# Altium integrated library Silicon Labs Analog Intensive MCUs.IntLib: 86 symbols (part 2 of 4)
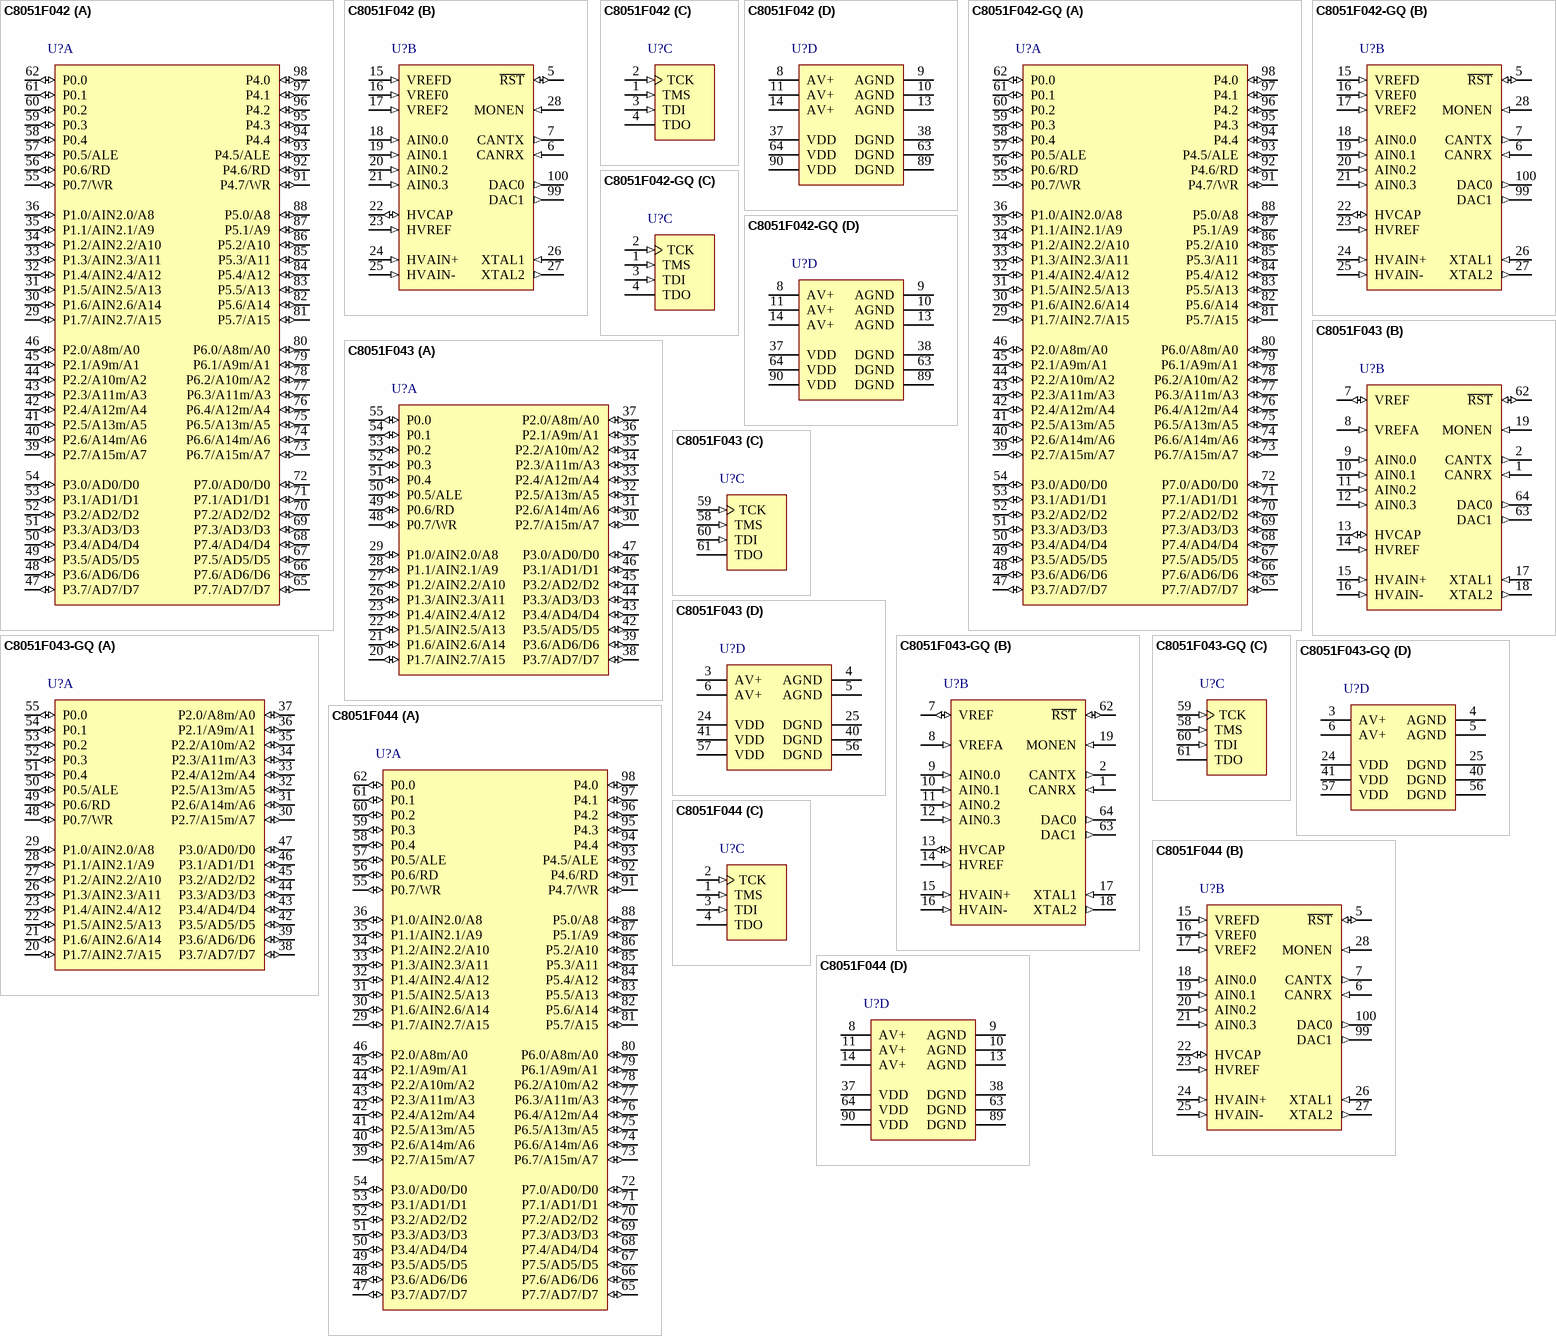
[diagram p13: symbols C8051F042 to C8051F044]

## C8051F042-GQ
designator U?
Mixed Signal 64KB ISP Flash MCU, 25 MIPS, 4352B RAM, 64 I/Os, 10-Bit & 8-Bit ADC, 12-Bit DAC, 100-Pin TQFP, Pb-Free; Manufacturer: Silicon Labs; PartNumber: C8051F042-GQ
footprint TQFP-100_N (Thin QFP, 100-Leads, Body 14x14mm, Pitch 0.5mm, IPC Medium Density)
footprint TQFP-100_L (Thin QFP, 100-Leads, Body 14x14mm, Pitch 0.5mm, IPC High Density)
footprint TQFP-100_M (Thin QFP, 100-Leads, Body 14x14mm, Pitch 0.5mm, IPC Low Density)
part A pins: 29 P1.7/AIN2.7/A15 (io), 30 P1.6/AIN2.6/A14 (io), 31 P1.5/AIN2.5/A13 (io), 32 P1.4/AIN2.4/A12 (io), 33 P1.3/AIN2.3/A11 (io), 34 P1.2/AIN2.2/A10 (io), 35 P1.1/AIN2.1/A9 (io), 36 P1.0/AIN2.0/A8 (io), 39 P2.7/A15m/A7 (io), 40 P2.6/A14m/A6 (io), 41 P2.5/A13m/A5 (io), 42 P2.4/A12m/A4 (io), 43 P2.3/A11m/A3 (io), 44 P2.2/A10m/A2 (io), 45 P2.1/A9m/A1 (io), 46 P2.0/A8m/A0 (io), 47 P3.7/AD7/D7 (io), 48 P3.6/AD6/D6 (io), 49 P3.5/AD5/D5 (io), 50 P3.4/AD4/D4 (io), 51 P3.3/AD3/D3 (io), 52 P3.2/AD2/D2 (io), 53 P3.1/AD1/D1 (io), 54 P3.0/AD0/D0 (io), 55 P0.7/WR (io), 56 P0.6/RD (io), 57 P0.5/ALE (io), 58 P0.4 (io), 59 P0.3 (io), 60 P0.2 (io), 61 P0.1 (io), 62 P0.0 (io), 65 P7.7/AD7/D7 (io), 66 P7.6/AD6/D6 (io), 67 P7.5/AD5/D5 (io), 68 P7.4/AD4/D4 (io), 69 P7.3/AD3/D3 (io), 70 P7.2/AD2/D2 (io), 71 P7.1/AD1/D1 (io), 72 P7.0/AD0/D0 (io), 73 P6.7/A15m/A7 (io), 74 P6.6/A14m/A6 (io), 75 P6.5/A13m/A5 (io), 76 P6.4/A12m/A4 (io), 77 P6.3/A11m/A3 (io), 78 P6.2/A10m/A2 (io), 79 P6.1/A9m/A1 (io), 80 P6.0/A8m/A0 (io), 81 P5.7/A15 (io), 82 P5.6/A14 (io), 83 P5.5/A13 (io), 84 P5.4/A12 (io), 85 P5.3/A11 (io), 86 P5.2/A10 (io), 87 P5.1/A9 (io), 88 P5.0/A8 (io), 91 P4.7/WR (io), 92 P4.6/RD (io), 93 P4.5/ALE (io), 94 P4.4 (io), 95 P4.3 (io), 96 P4.2 (io), 97 P4.1 (io), 98 P4.0 (io)
part B pins: 5 ~{RST} (io), 6 CANRX (in), 7 CANTX (out), 15 VREFD (in), 16 VREF0 (in), 17 VREF2 (in), 18 AIN0.0 (in), 19 AIN0.1 (in), 20 AIN0.2 (in), 21 AIN0.3 (in), 22 HVCAP (io), 23 HVREF (in), 24 HVAIN+ (in), 25 HVAIN- (in), 26 XTAL1 (in), 27 XTAL2 (out), 28 MONEN (in), 99 DAC1 (out), 100 DAC0 (out)
part C pins: 1 TMS (in), 2 TCK (in), 3 TDI (in), 4 TDO (hiz)
part D pins: 8 AV+ (power), 9 AGND (power), 10 AGND (power), 11 AV+ (power), 13 AGND (power), 14 AV+ (power), 37 VDD (power), 38 DGND (power), 63 DGND (power), 64 VDD (power), 89 DGND (power), 90 VDD (power)

## C8051F043
designator U?
Mixed Signal 64KB ISP Flash MCU, 25 MIPS, 4352B RAM, 32 I/Os, 10-Bit & 8-Bit ADC, 12-Bit DAC, 64-Pin TQFP; Manufacturer: Silicon Labs; PartNumber: C8051F043
footprint TQFP-64_N (Thin QFP, 64-Leads, Body 10x10mm, Pitch 0.5mm, IPC Medium Density)
footprint TQFP-64_L (Thin QFP, 64-Leads, Body 10x10mm, Pitch 0.5mm, IPC High Density)
footprint TQFP-64_M (Thin QFP, 64-Leads, Body 10x10mm, Pitch 0.5mm, IPC Low Density)
part A pins: 20 P1.7/AIN2.7/A15 (io), 21 P1.6/AIN2.6/A14 (io), 22 P1.5/AIN2.5/A13 (io), 23 P1.4/AIN2.4/A12 (io), 26 P1.3/AIN2.3/A11 (io), 27 P1.2/AIN2.2/A10 (io), 28 P1.1/AIN2.1/A9 (io), 29 P1.0/AIN2.0/A8 (io), 30 P2.7/A15m/A7 (io), 31 P2.6/A14m/A6 (io), 32 P2.5/A13m/A5 (io), 33 P2.4/A12m/A4 (io), 34 P2.3/A11m/A3 (io), 35 P2.2/A10m/A2 (io), 36 P2.1/A9m/A1 (io), 37 P2.0/A8m/A0 (io), 38 P3.7/AD7/D7 (io), 39 P3.6/AD6/D6 (io), 42 P3.5/AD5/D5 (io), 43 P3.4/AD4/D4 (io), 44 P3.3/AD3/D3 (io), 45 P3.2/AD2/D2 (io), 46 P3.1/AD1/D1 (io), 47 P3.0/AD0/D0 (io), 48 P0.7/WR (io), 49 P0.6/RD (io), 50 P0.5/ALE (io), 51 P0.4 (io), 52 P0.3 (io), 53 P0.2 (io), 54 P0.1 (io), 55 P0.0 (io)
part B pins: 1 CANRX (in), 2 CANTX (out), 7 VREF (io), 8 VREFA (in), 9 AIN0.0 (in), 10 AIN0.1 (in), 11 AIN0.2 (in), 12 AIN0.3 (in), 13 HVCAP (io), 14 HVREF (in), 15 HVAIN+ (in), 16 HVAIN- (in), 17 XTAL1 (in), 18 XTAL2 (out), 19 MONEN (in), 62 ~{RST} (io), 63 DAC1 (out), 64 DAC0 (out)
part C pins: 58 TMS (in), 59 TCK (in), 60 TDI (in), 61 TDO (hiz)
part D pins: 3 AV+ (power), 4 AGND (power), 5 AGND (power), 6 AV+ (power), 24 VDD (power), 25 DGND (power), 40 DGND (power), 41 VDD (power), 56 DGND (power), 57 VDD (power)

## C8051F043-GQ
designator U?
Mixed Signal 64KB ISP Flash MCU, 25 MIPS, 4352B RAM, 32 I/Os, 10-Bit & 8-Bit ADC, 12-Bit DAC, 64-Pin TQFP, Pb-Free; Manufacturer: Silicon Labs; PartNumber: C8051F043-GQ
footprint TQFP-64_N (Thin QFP, 64-Leads, Body 10x10mm, Pitch 0.5mm, IPC Medium Density)
footprint TQFP-64_L (Thin QFP, 64-Leads, Body 10x10mm, Pitch 0.5mm, IPC High Density)
footprint TQFP-64_M (Thin QFP, 64-Leads, Body 10x10mm, Pitch 0.5mm, IPC Low Density)
part A pins: 20 P1.7/AIN2.7/A15 (io), 21 P1.6/AIN2.6/A14 (io), 22 P1.5/AIN2.5/A13 (io), 23 P1.4/AIN2.4/A12 (io), 26 P1.3/AIN2.3/A11 (io), 27 P1.2/AIN2.2/A10 (io), 28 P1.1/AIN2.1/A9 (io), 29 P1.0/AIN2.0/A8 (io), 30 P2.7/A15m/A7 (io), 31 P2.6/A14m/A6 (io), 32 P2.5/A13m/A5 (io), 33 P2.4/A12m/A4 (io), 34 P2.3/A11m/A3 (io), 35 P2.2/A10m/A2 (io), 36 P2.1/A9m/A1 (io), 37 P2.0/A8m/A0 (io), 38 P3.7/AD7/D7 (io), 39 P3.6/AD6/D6 (io), 42 P3.5/AD5/D5 (io), 43 P3.4/AD4/D4 (io), 44 P3.3/AD3/D3 (io), 45 P3.2/AD2/D2 (io), 46 P3.1/AD1/D1 (io), 47 P3.0/AD0/D0 (io), 48 P0.7/WR (io), 49 P0.6/RD (io), 50 P0.5/ALE (io), 51 P0.4 (io), 52 P0.3 (io), 53 P0.2 (io), 54 P0.1 (io), 55 P0.0 (io)
part B pins: 1 CANRX (in), 2 CANTX (out), 7 VREF (io), 8 VREFA (in), 9 AIN0.0 (in), 10 AIN0.1 (in), 11 AIN0.2 (in), 12 AIN0.3 (in), 13 HVCAP (io), 14 HVREF (in), 15 HVAIN+ (in), 16 HVAIN- (in), 17 XTAL1 (in), 18 XTAL2 (out), 19 MONEN (in), 62 ~{RST} (io), 63 DAC1 (out), 64 DAC0 (out)
part C pins: 58 TMS (in), 59 TCK (in), 60 TDI (in), 61 TDO (hiz)
part D pins: 3 AV+ (power), 4 AGND (power), 5 AGND (power), 6 AV+ (power), 24 VDD (power), 25 DGND (power), 40 DGND (power), 41 VDD (power), 56 DGND (power), 57 VDD (power)

## C8051F044
designator U?
Mixed Signal 64KB ISP Flash MCU, 25 MIPS, 4352B RAM, 64 I/Os, 10-Bit ADC, 100-Pin TQFP; Manufacturer: Silicon Labs; PartNumber: C8051F044
footprint TQFP-100_N (Thin QFP, 100-Leads, Body 14x14mm, Pitch 0.5mm, IPC Medium Density)
footprint TQFP-100_L (Thin QFP, 100-Leads, Body 14x14mm, Pitch 0.5mm, IPC High Density)
footprint TQFP-100_M (Thin QFP, 100-Leads, Body 14x14mm, Pitch 0.5mm, IPC Low Density)
part A pins: 29 P1.7/AIN2.7/A15 (io), 30 P1.6/AIN2.6/A14 (io), 31 P1.5/AIN2.5/A13 (io), 32 P1.4/AIN2.4/A12 (io), 33 P1.3/AIN2.3/A11 (io), 34 P1.2/AIN2.2/A10 (io), 35 P1.1/AIN2.1/A9 (io), 36 P1.0/AIN2.0/A8 (io), 39 P2.7/A15m/A7 (io), 40 P2.6/A14m/A6 (io), 41 P2.5/A13m/A5 (io), 42 P2.4/A12m/A4 (io), 43 P2.3/A11m/A3 (io), 44 P2.2/A10m/A2 (io), 45 P2.1/A9m/A1 (io), 46 P2.0/A8m/A0 (io), 47 P3.7/AD7/D7 (io), 48 P3.6/AD6/D6 (io), 49 P3.5/AD5/D5 (io), 50 P3.4/AD4/D4 (io), 51 P3.3/AD3/D3 (io), 52 P3.2/AD2/D2 (io), 53 P3.1/AD1/D1 (io), 54 P3.0/AD0/D0 (io), 55 P0.7/WR (io), 56 P0.6/RD (io), 57 P0.5/ALE (io), 58 P0.4 (io), 59 P0.3 (io), 60 P0.2 (io), 61 P0.1 (io), 62 P0.0 (io), 65 P7.7/AD7/D7 (io), 66 P7.6/AD6/D6 (io), 67 P7.5/AD5/D5 (io), 68 P7.4/AD4/D4 (io), 69 P7.3/AD3/D3 (io), 70 P7.2/AD2/D2 (io), 71 P7.1/AD1/D1 (io), 72 P7.0/AD0/D0 (io), 73 P6.7/A15m/A7 (io), 74 P6.6/A14m/A6 (io), 75 P6.5/A13m/A5 (io), 76 P6.4/A12m/A4 (io), 77 P6.3/A11m/A3 (io), 78 P6.2/A10m/A2 (io), 79 P6.1/A9m/A1 (io), 80 P6.0/A8m/A0 (io), 81 P5.7/A15 (io), 82 P5.6/A14 (io), 83 P5.5/A13 (io), 84 P5.4/A12 (io), 85 P5.3/A11 (io), 86 P5.2/A10 (io), 87 P5.1/A9 (io), 88 P5.0/A8 (io), 91 P4.7/WR (io), 92 P4.6/RD (io), 93 P4.5/ALE (io), 94 P4.4 (io), 95 P4.3 (io), 96 P4.2 (io), 97 P4.1 (io), 98 P4.0 (io)
part B pins: 5 ~{RST} (io), 6 CANRX (in), 7 CANTX (out), 15 VREFD (in), 16 VREF0 (in), 17 VREF2 (in), 18 AIN0.0 (in), 19 AIN0.1 (in), 20 AIN0.2 (in), 21 AIN0.3 (in), 22 HVCAP (io), 23 HVREF (in), 24 HVAIN+ (in), 25 HVAIN- (in), 26 XTAL1 (in), 27 XTAL2 (out), 28 MONEN (in), 99 DAC1 (out), 100 DAC0 (out)
part C pins: 1 TMS (in), 2 TCK (in), 3 TDI (in), 4 TDO (hiz)
part D pins: 8 AV+ (power), 9 AGND (power), 10 AGND (power), 11 AV+ (power), 13 AGND (power), 14 AV+ (power), 37 VDD (power), 38 DGND (power), 63 DGND (power), 64 VDD (power), 89 DGND (power), 90 VDD (power)

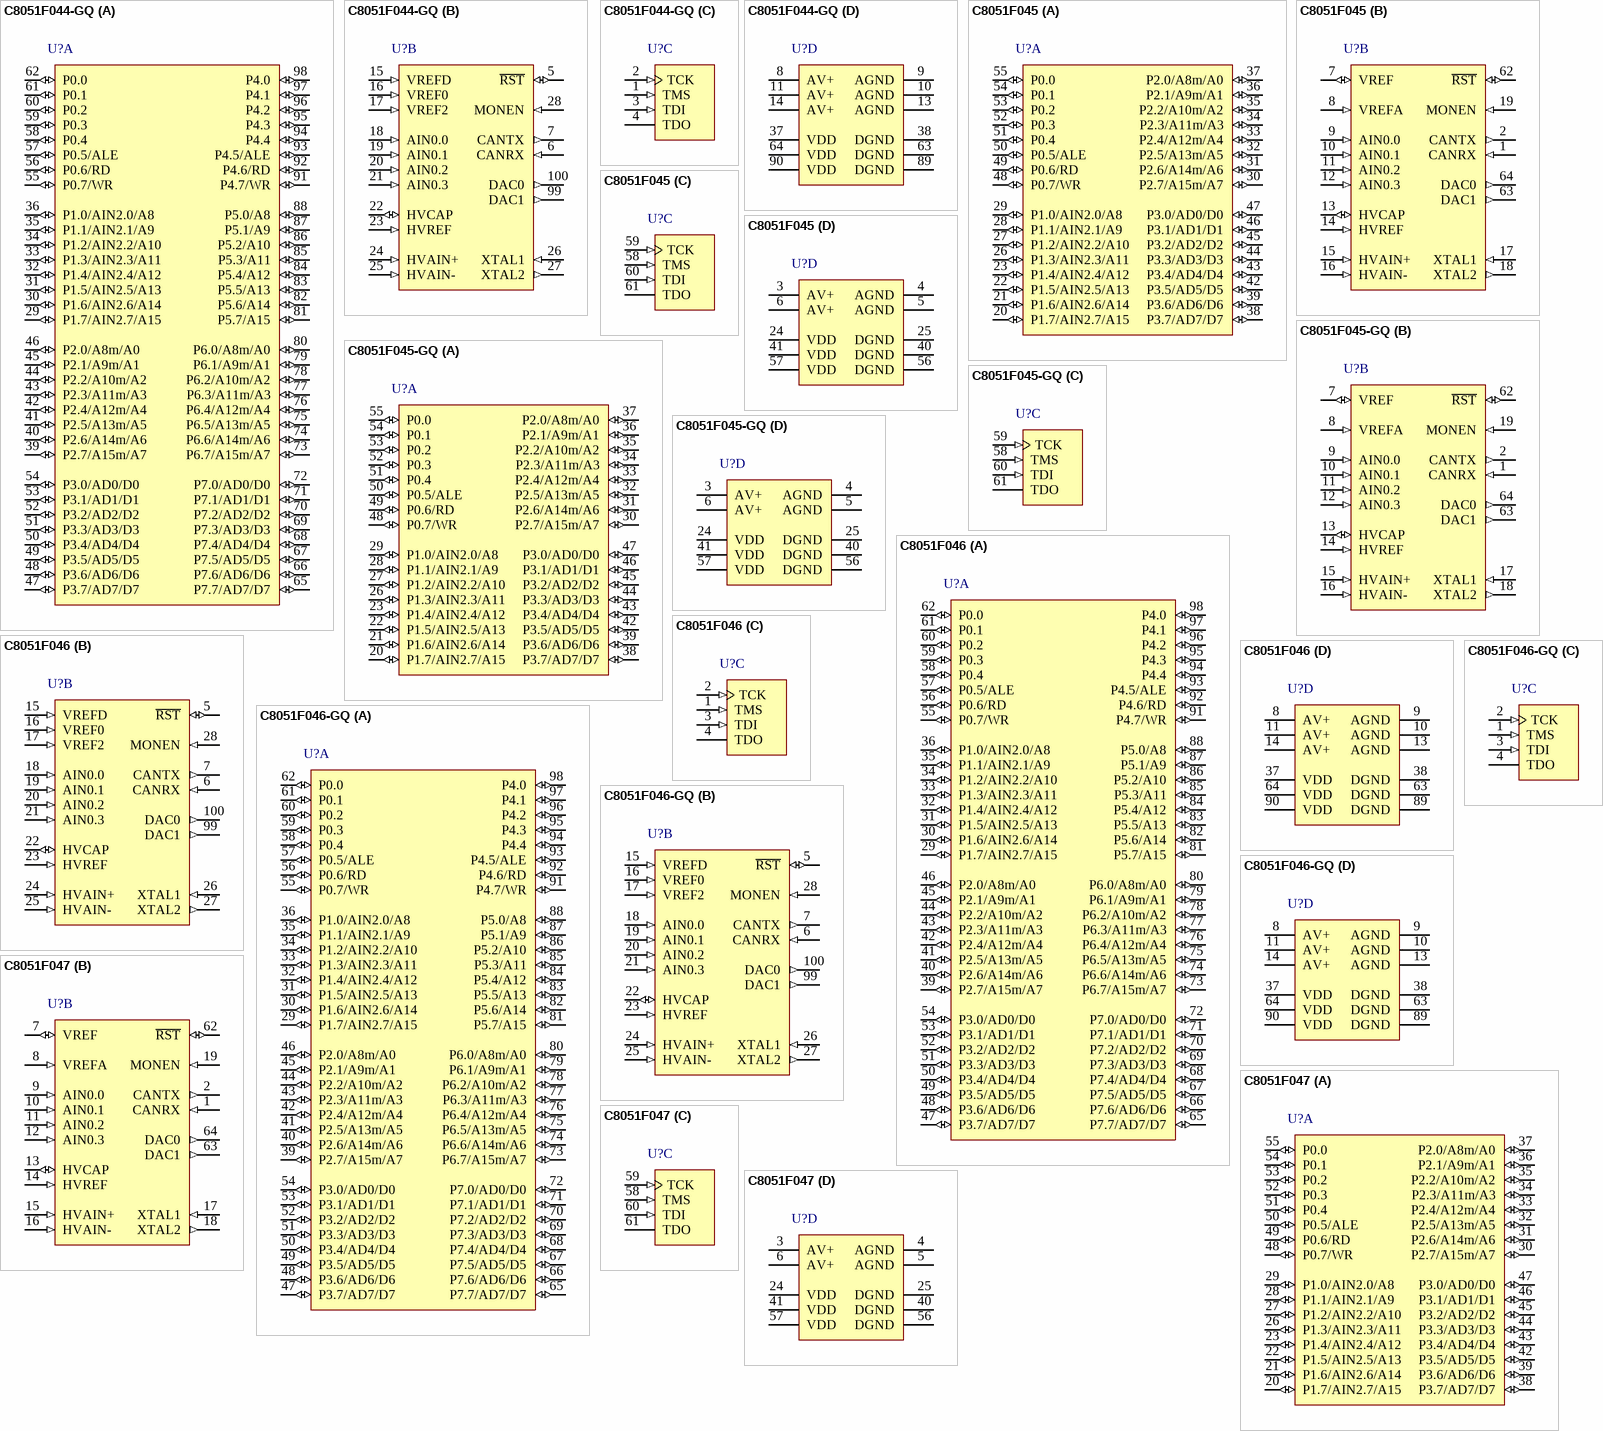
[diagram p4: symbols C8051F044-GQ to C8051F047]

## C8051F044-GQ
designator U?
Mixed Signal 64KB ISP Flash MCU, 25 MIPS, 4352B RAM, 64 I/Os, 10-Bit ADC, 100-Pin TQFP, Pb-Free; Manufacturer: Silicon Labs; PartNumber: C8051F044-GQ
footprint TQFP-100_N (Thin QFP, 100-Leads, Body 14x14mm, Pitch 0.5mm, IPC Medium Density)
footprint TQFP-100_L (Thin QFP, 100-Leads, Body 14x14mm, Pitch 0.5mm, IPC High Density)
footprint TQFP-100_M (Thin QFP, 100-Leads, Body 14x14mm, Pitch 0.5mm, IPC Low Density)
part A pins: 29 P1.7/AIN2.7/A15 (io), 30 P1.6/AIN2.6/A14 (io), 31 P1.5/AIN2.5/A13 (io), 32 P1.4/AIN2.4/A12 (io), 33 P1.3/AIN2.3/A11 (io), 34 P1.2/AIN2.2/A10 (io), 35 P1.1/AIN2.1/A9 (io), 36 P1.0/AIN2.0/A8 (io), 39 P2.7/A15m/A7 (io), 40 P2.6/A14m/A6 (io), 41 P2.5/A13m/A5 (io), 42 P2.4/A12m/A4 (io), 43 P2.3/A11m/A3 (io), 44 P2.2/A10m/A2 (io), 45 P2.1/A9m/A1 (io), 46 P2.0/A8m/A0 (io), 47 P3.7/AD7/D7 (io), 48 P3.6/AD6/D6 (io), 49 P3.5/AD5/D5 (io), 50 P3.4/AD4/D4 (io), 51 P3.3/AD3/D3 (io), 52 P3.2/AD2/D2 (io), 53 P3.1/AD1/D1 (io), 54 P3.0/AD0/D0 (io), 55 P0.7/WR (io), 56 P0.6/RD (io), 57 P0.5/ALE (io), 58 P0.4 (io), 59 P0.3 (io), 60 P0.2 (io), 61 P0.1 (io), 62 P0.0 (io), 65 P7.7/AD7/D7 (io), 66 P7.6/AD6/D6 (io), 67 P7.5/AD5/D5 (io), 68 P7.4/AD4/D4 (io), 69 P7.3/AD3/D3 (io), 70 P7.2/AD2/D2 (io), 71 P7.1/AD1/D1 (io), 72 P7.0/AD0/D0 (io), 73 P6.7/A15m/A7 (io), 74 P6.6/A14m/A6 (io), 75 P6.5/A13m/A5 (io), 76 P6.4/A12m/A4 (io), 77 P6.3/A11m/A3 (io), 78 P6.2/A10m/A2 (io), 79 P6.1/A9m/A1 (io), 80 P6.0/A8m/A0 (io), 81 P5.7/A15 (io), 82 P5.6/A14 (io), 83 P5.5/A13 (io), 84 P5.4/A12 (io), 85 P5.3/A11 (io), 86 P5.2/A10 (io), 87 P5.1/A9 (io), 88 P5.0/A8 (io), 91 P4.7/WR (io), 92 P4.6/RD (io), 93 P4.5/ALE (io), 94 P4.4 (io), 95 P4.3 (io), 96 P4.2 (io), 97 P4.1 (io), 98 P4.0 (io)
part B pins: 5 ~{RST} (io), 6 CANRX (in), 7 CANTX (out), 15 VREFD (in), 16 VREF0 (in), 17 VREF2 (in), 18 AIN0.0 (in), 19 AIN0.1 (in), 20 AIN0.2 (in), 21 AIN0.3 (in), 22 HVCAP (io), 23 HVREF (in), 24 HVAIN+ (in), 25 HVAIN- (in), 26 XTAL1 (in), 27 XTAL2 (out), 28 MONEN (in), 99 DAC1 (out), 100 DAC0 (out)
part C pins: 1 TMS (in), 2 TCK (in), 3 TDI (in), 4 TDO (hiz)
part D pins: 8 AV+ (power), 9 AGND (power), 10 AGND (power), 11 AV+ (power), 13 AGND (power), 14 AV+ (power), 37 VDD (power), 38 DGND (power), 63 DGND (power), 64 VDD (power), 89 DGND (power), 90 VDD (power)

## C8051F045
designator U?
Mixed Signal 64KB ISP Flash MCU, 25 MIPS, 4352B RAM, 32 I/Os, 10-Bit ADC, 64-Pin TQFP; Manufacturer: Silicon Labs; PartNumber: C8051F045
footprint TQFP-64_N (Thin QFP, 64-Leads, Body 10x10mm, Pitch 0.5mm, IPC Medium Density)
footprint TQFP-64_L (Thin QFP, 64-Leads, Body 10x10mm, Pitch 0.5mm, IPC High Density)
footprint TQFP-64_M (Thin QFP, 64-Leads, Body 10x10mm, Pitch 0.5mm, IPC Low Density)
part A pins: 20 P1.7/AIN2.7/A15 (io), 21 P1.6/AIN2.6/A14 (io), 22 P1.5/AIN2.5/A13 (io), 23 P1.4/AIN2.4/A12 (io), 26 P1.3/AIN2.3/A11 (io), 27 P1.2/AIN2.2/A10 (io), 28 P1.1/AIN2.1/A9 (io), 29 P1.0/AIN2.0/A8 (io), 30 P2.7/A15m/A7 (io), 31 P2.6/A14m/A6 (io), 32 P2.5/A13m/A5 (io), 33 P2.4/A12m/A4 (io), 34 P2.3/A11m/A3 (io), 35 P2.2/A10m/A2 (io), 36 P2.1/A9m/A1 (io), 37 P2.0/A8m/A0 (io), 38 P3.7/AD7/D7 (io), 39 P3.6/AD6/D6 (io), 42 P3.5/AD5/D5 (io), 43 P3.4/AD4/D4 (io), 44 P3.3/AD3/D3 (io), 45 P3.2/AD2/D2 (io), 46 P3.1/AD1/D1 (io), 47 P3.0/AD0/D0 (io), 48 P0.7/WR (io), 49 P0.6/RD (io), 50 P0.5/ALE (io), 51 P0.4 (io), 52 P0.3 (io), 53 P0.2 (io), 54 P0.1 (io), 55 P0.0 (io)
part B pins: 1 CANRX (in), 2 CANTX (out), 7 VREF (io), 8 VREFA (in), 9 AIN0.0 (in), 10 AIN0.1 (in), 11 AIN0.2 (in), 12 AIN0.3 (in), 13 HVCAP (io), 14 HVREF (in), 15 HVAIN+ (in), 16 HVAIN- (in), 17 XTAL1 (in), 18 XTAL2 (out), 19 MONEN (in), 62 ~{RST} (io), 63 DAC1 (out), 64 DAC0 (out)
part C pins: 58 TMS (in), 59 TCK (in), 60 TDI (in), 61 TDO (hiz)
part D pins: 3 AV+ (power), 4 AGND (power), 5 AGND (power), 6 AV+ (power), 24 VDD (power), 25 DGND (power), 40 DGND (power), 41 VDD (power), 56 DGND (power), 57 VDD (power)

## C8051F045-GQ
designator U?
Mixed Signal 64KB ISP Flash MCU, 25 MIPS, 4352B RAM, 32 I/Os, 10-Bit ADC, 64-Pin TQFP, Pb-Free; Manufacturer: Silicon Labs; PartNumber: C8051F045-GQ
footprint TQFP-64_N (Thin QFP, 64-Leads, Body 10x10mm, Pitch 0.5mm, IPC Medium Density)
footprint TQFP-64_L (Thin QFP, 64-Leads, Body 10x10mm, Pitch 0.5mm, IPC High Density)
footprint TQFP-64_M (Thin QFP, 64-Leads, Body 10x10mm, Pitch 0.5mm, IPC Low Density)
part A pins: 20 P1.7/AIN2.7/A15 (io), 21 P1.6/AIN2.6/A14 (io), 22 P1.5/AIN2.5/A13 (io), 23 P1.4/AIN2.4/A12 (io), 26 P1.3/AIN2.3/A11 (io), 27 P1.2/AIN2.2/A10 (io), 28 P1.1/AIN2.1/A9 (io), 29 P1.0/AIN2.0/A8 (io), 30 P2.7/A15m/A7 (io), 31 P2.6/A14m/A6 (io), 32 P2.5/A13m/A5 (io), 33 P2.4/A12m/A4 (io), 34 P2.3/A11m/A3 (io), 35 P2.2/A10m/A2 (io), 36 P2.1/A9m/A1 (io), 37 P2.0/A8m/A0 (io), 38 P3.7/AD7/D7 (io), 39 P3.6/AD6/D6 (io), 42 P3.5/AD5/D5 (io), 43 P3.4/AD4/D4 (io), 44 P3.3/AD3/D3 (io), 45 P3.2/AD2/D2 (io), 46 P3.1/AD1/D1 (io), 47 P3.0/AD0/D0 (io), 48 P0.7/WR (io), 49 P0.6/RD (io), 50 P0.5/ALE (io), 51 P0.4 (io), 52 P0.3 (io), 53 P0.2 (io), 54 P0.1 (io), 55 P0.0 (io)
part B pins: 1 CANRX (in), 2 CANTX (out), 7 VREF (io), 8 VREFA (in), 9 AIN0.0 (in), 10 AIN0.1 (in), 11 AIN0.2 (in), 12 AIN0.3 (in), 13 HVCAP (io), 14 HVREF (in), 15 HVAIN+ (in), 16 HVAIN- (in), 17 XTAL1 (in), 18 XTAL2 (out), 19 MONEN (in), 62 ~{RST} (io), 63 DAC1 (out), 64 DAC0 (out)
part C pins: 58 TMS (in), 59 TCK (in), 60 TDI (in), 61 TDO (hiz)
part D pins: 3 AV+ (power), 4 AGND (power), 5 AGND (power), 6 AV+ (power), 24 VDD (power), 25 DGND (power), 40 DGND (power), 41 VDD (power), 56 DGND (power), 57 VDD (power)

## C8051F046
designator U?
Mixed Signal 32KB ISP Flash MCU, 25 MIPS, 4352B RAM, 64 I/Os, 10-Bit ADC, 100-Pin TQFP; Manufacturer: Silicon Labs; PartNumber: C8051F046
footprint TQFP-100_N (Thin QFP, 100-Leads, Body 14x14mm, Pitch 0.5mm, IPC Medium Density)
footprint TQFP-100_L (Thin QFP, 100-Leads, Body 14x14mm, Pitch 0.5mm, IPC High Density)
footprint TQFP-100_M (Thin QFP, 100-Leads, Body 14x14mm, Pitch 0.5mm, IPC Low Density)
part A pins: 29 P1.7/AIN2.7/A15 (io), 30 P1.6/AIN2.6/A14 (io), 31 P1.5/AIN2.5/A13 (io), 32 P1.4/AIN2.4/A12 (io), 33 P1.3/AIN2.3/A11 (io), 34 P1.2/AIN2.2/A10 (io), 35 P1.1/AIN2.1/A9 (io), 36 P1.0/AIN2.0/A8 (io), 39 P2.7/A15m/A7 (io), 40 P2.6/A14m/A6 (io), 41 P2.5/A13m/A5 (io), 42 P2.4/A12m/A4 (io), 43 P2.3/A11m/A3 (io), 44 P2.2/A10m/A2 (io), 45 P2.1/A9m/A1 (io), 46 P2.0/A8m/A0 (io), 47 P3.7/AD7/D7 (io), 48 P3.6/AD6/D6 (io), 49 P3.5/AD5/D5 (io), 50 P3.4/AD4/D4 (io), 51 P3.3/AD3/D3 (io), 52 P3.2/AD2/D2 (io), 53 P3.1/AD1/D1 (io), 54 P3.0/AD0/D0 (io), 55 P0.7/WR (io), 56 P0.6/RD (io), 57 P0.5/ALE (io), 58 P0.4 (io), 59 P0.3 (io), 60 P0.2 (io), 61 P0.1 (io), 62 P0.0 (io), 65 P7.7/AD7/D7 (io), 66 P7.6/AD6/D6 (io), 67 P7.5/AD5/D5 (io), 68 P7.4/AD4/D4 (io), 69 P7.3/AD3/D3 (io), 70 P7.2/AD2/D2 (io), 71 P7.1/AD1/D1 (io), 72 P7.0/AD0/D0 (io), 73 P6.7/A15m/A7 (io), 74 P6.6/A14m/A6 (io), 75 P6.5/A13m/A5 (io), 76 P6.4/A12m/A4 (io), 77 P6.3/A11m/A3 (io), 78 P6.2/A10m/A2 (io), 79 P6.1/A9m/A1 (io), 80 P6.0/A8m/A0 (io), 81 P5.7/A15 (io), 82 P5.6/A14 (io), 83 P5.5/A13 (io), 84 P5.4/A12 (io), 85 P5.3/A11 (io), 86 P5.2/A10 (io), 87 P5.1/A9 (io), 88 P5.0/A8 (io), 91 P4.7/WR (io), 92 P4.6/RD (io), 93 P4.5/ALE (io), 94 P4.4 (io), 95 P4.3 (io), 96 P4.2 (io), 97 P4.1 (io), 98 P4.0 (io)
part B pins: 5 ~{RST} (io), 6 CANRX (in), 7 CANTX (out), 15 VREFD (in), 16 VREF0 (in), 17 VREF2 (in), 18 AIN0.0 (in), 19 AIN0.1 (in), 20 AIN0.2 (in), 21 AIN0.3 (in), 22 HVCAP (io), 23 HVREF (in), 24 HVAIN+ (in), 25 HVAIN- (in), 26 XTAL1 (in), 27 XTAL2 (out), 28 MONEN (in), 99 DAC1 (out), 100 DAC0 (out)
part C pins: 1 TMS (in), 2 TCK (in), 3 TDI (in), 4 TDO (hiz)
part D pins: 8 AV+ (power), 9 AGND (power), 10 AGND (power), 11 AV+ (power), 13 AGND (power), 14 AV+ (power), 37 VDD (power), 38 DGND (power), 63 DGND (power), 64 VDD (power), 89 DGND (power), 90 VDD (power)

## C8051F046-GQ
designator U?
Mixed Signal 32KB ISP Flash MCU, 25 MIPS, 4352B RAM, 64 I/Os, 10-Bit ADC, 100-Pin TQFP, Pb-Free; Manufacturer: Silicon Labs; PartNumber: C8051F046-GQ
footprint TQFP-100_N (Thin QFP, 100-Leads, Body 14x14mm, Pitch 0.5mm, IPC Medium Density)
footprint TQFP-100_L (Thin QFP, 100-Leads, Body 14x14mm, Pitch 0.5mm, IPC High Density)
footprint TQFP-100_M (Thin QFP, 100-Leads, Body 14x14mm, Pitch 0.5mm, IPC Low Density)
part A pins: 29 P1.7/AIN2.7/A15 (io), 30 P1.6/AIN2.6/A14 (io), 31 P1.5/AIN2.5/A13 (io), 32 P1.4/AIN2.4/A12 (io), 33 P1.3/AIN2.3/A11 (io), 34 P1.2/AIN2.2/A10 (io), 35 P1.1/AIN2.1/A9 (io), 36 P1.0/AIN2.0/A8 (io), 39 P2.7/A15m/A7 (io), 40 P2.6/A14m/A6 (io), 41 P2.5/A13m/A5 (io), 42 P2.4/A12m/A4 (io), 43 P2.3/A11m/A3 (io), 44 P2.2/A10m/A2 (io), 45 P2.1/A9m/A1 (io), 46 P2.0/A8m/A0 (io), 47 P3.7/AD7/D7 (io), 48 P3.6/AD6/D6 (io), 49 P3.5/AD5/D5 (io), 50 P3.4/AD4/D4 (io), 51 P3.3/AD3/D3 (io), 52 P3.2/AD2/D2 (io), 53 P3.1/AD1/D1 (io), 54 P3.0/AD0/D0 (io), 55 P0.7/WR (io), 56 P0.6/RD (io), 57 P0.5/ALE (io), 58 P0.4 (io), 59 P0.3 (io), 60 P0.2 (io), 61 P0.1 (io), 62 P0.0 (io), 65 P7.7/AD7/D7 (io), 66 P7.6/AD6/D6 (io), 67 P7.5/AD5/D5 (io), 68 P7.4/AD4/D4 (io), 69 P7.3/AD3/D3 (io), 70 P7.2/AD2/D2 (io), 71 P7.1/AD1/D1 (io), 72 P7.0/AD0/D0 (io), 73 P6.7/A15m/A7 (io), 74 P6.6/A14m/A6 (io), 75 P6.5/A13m/A5 (io), 76 P6.4/A12m/A4 (io), 77 P6.3/A11m/A3 (io), 78 P6.2/A10m/A2 (io), 79 P6.1/A9m/A1 (io), 80 P6.0/A8m/A0 (io), 81 P5.7/A15 (io), 82 P5.6/A14 (io), 83 P5.5/A13 (io), 84 P5.4/A12 (io), 85 P5.3/A11 (io), 86 P5.2/A10 (io), 87 P5.1/A9 (io), 88 P5.0/A8 (io), 91 P4.7/WR (io), 92 P4.6/RD (io), 93 P4.5/ALE (io), 94 P4.4 (io), 95 P4.3 (io), 96 P4.2 (io), 97 P4.1 (io), 98 P4.0 (io)
part B pins: 5 ~{RST} (io), 6 CANRX (in), 7 CANTX (out), 15 VREFD (in), 16 VREF0 (in), 17 VREF2 (in), 18 AIN0.0 (in), 19 AIN0.1 (in), 20 AIN0.2 (in), 21 AIN0.3 (in), 22 HVCAP (io), 23 HVREF (in), 24 HVAIN+ (in), 25 HVAIN- (in), 26 XTAL1 (in), 27 XTAL2 (out), 28 MONEN (in), 99 DAC1 (out), 100 DAC0 (out)
part C pins: 1 TMS (in), 2 TCK (in), 3 TDI (in), 4 TDO (hiz)
part D pins: 8 AV+ (power), 9 AGND (power), 10 AGND (power), 11 AV+ (power), 13 AGND (power), 14 AV+ (power), 37 VDD (power), 38 DGND (power), 63 DGND (power), 64 VDD (power), 89 DGND (power), 90 VDD (power)

## C8051F047
designator U?
Mixed Signal 32KB ISP Flash MCU, 25 MIPS, 4352B RAM, 32 I/Os, 10-Bit ADC, 64-Pin TQFP; Manufacturer: Silicon Labs; PartNumber: C8051F047
footprint TQFP-64_N (Thin QFP, 64-Leads, Body 10x10mm, Pitch 0.5mm, IPC Medium Density)
footprint TQFP-64_L (Thin QFP, 64-Leads, Body 10x10mm, Pitch 0.5mm, IPC High Density)
footprint TQFP-64_M (Thin QFP, 64-Leads, Body 10x10mm, Pitch 0.5mm, IPC Low Density)
part A pins: 20 P1.7/AIN2.7/A15 (io), 21 P1.6/AIN2.6/A14 (io), 22 P1.5/AIN2.5/A13 (io), 23 P1.4/AIN2.4/A12 (io), 26 P1.3/AIN2.3/A11 (io), 27 P1.2/AIN2.2/A10 (io), 28 P1.1/AIN2.1/A9 (io), 29 P1.0/AIN2.0/A8 (io), 30 P2.7/A15m/A7 (io), 31 P2.6/A14m/A6 (io), 32 P2.5/A13m/A5 (io), 33 P2.4/A12m/A4 (io), 34 P2.3/A11m/A3 (io), 35 P2.2/A10m/A2 (io), 36 P2.1/A9m/A1 (io), 37 P2.0/A8m/A0 (io), 38 P3.7/AD7/D7 (io), 39 P3.6/AD6/D6 (io), 42 P3.5/AD5/D5 (io), 43 P3.4/AD4/D4 (io), 44 P3.3/AD3/D3 (io), 45 P3.2/AD2/D2 (io), 46 P3.1/AD1/D1 (io), 47 P3.0/AD0/D0 (io), 48 P0.7/WR (io), 49 P0.6/RD (io), 50 P0.5/ALE (io), 51 P0.4 (io), 52 P0.3 (io), 53 P0.2 (io), 54 P0.1 (io), 55 P0.0 (io)
part B pins: 1 CANRX (in), 2 CANTX (out), 7 VREF (io), 8 VREFA (in), 9 AIN0.0 (in), 10 AIN0.1 (in), 11 AIN0.2 (in), 12 AIN0.3 (in), 13 HVCAP (io), 14 HVREF (in), 15 HVAIN+ (in), 16 HVAIN- (in), 17 XTAL1 (in), 18 XTAL2 (out), 19 MONEN (in), 62 ~{RST} (io), 63 DAC1 (out), 64 DAC0 (out)
part C pins: 58 TMS (in), 59 TCK (in), 60 TDI (in), 61 TDO (hiz)
part D pins: 3 AV+ (power), 4 AGND (power), 5 AGND (power), 6 AV+ (power), 24 VDD (power), 25 DGND (power), 40 DGND (power), 41 VDD (power), 56 DGND (power), 57 VDD (power)

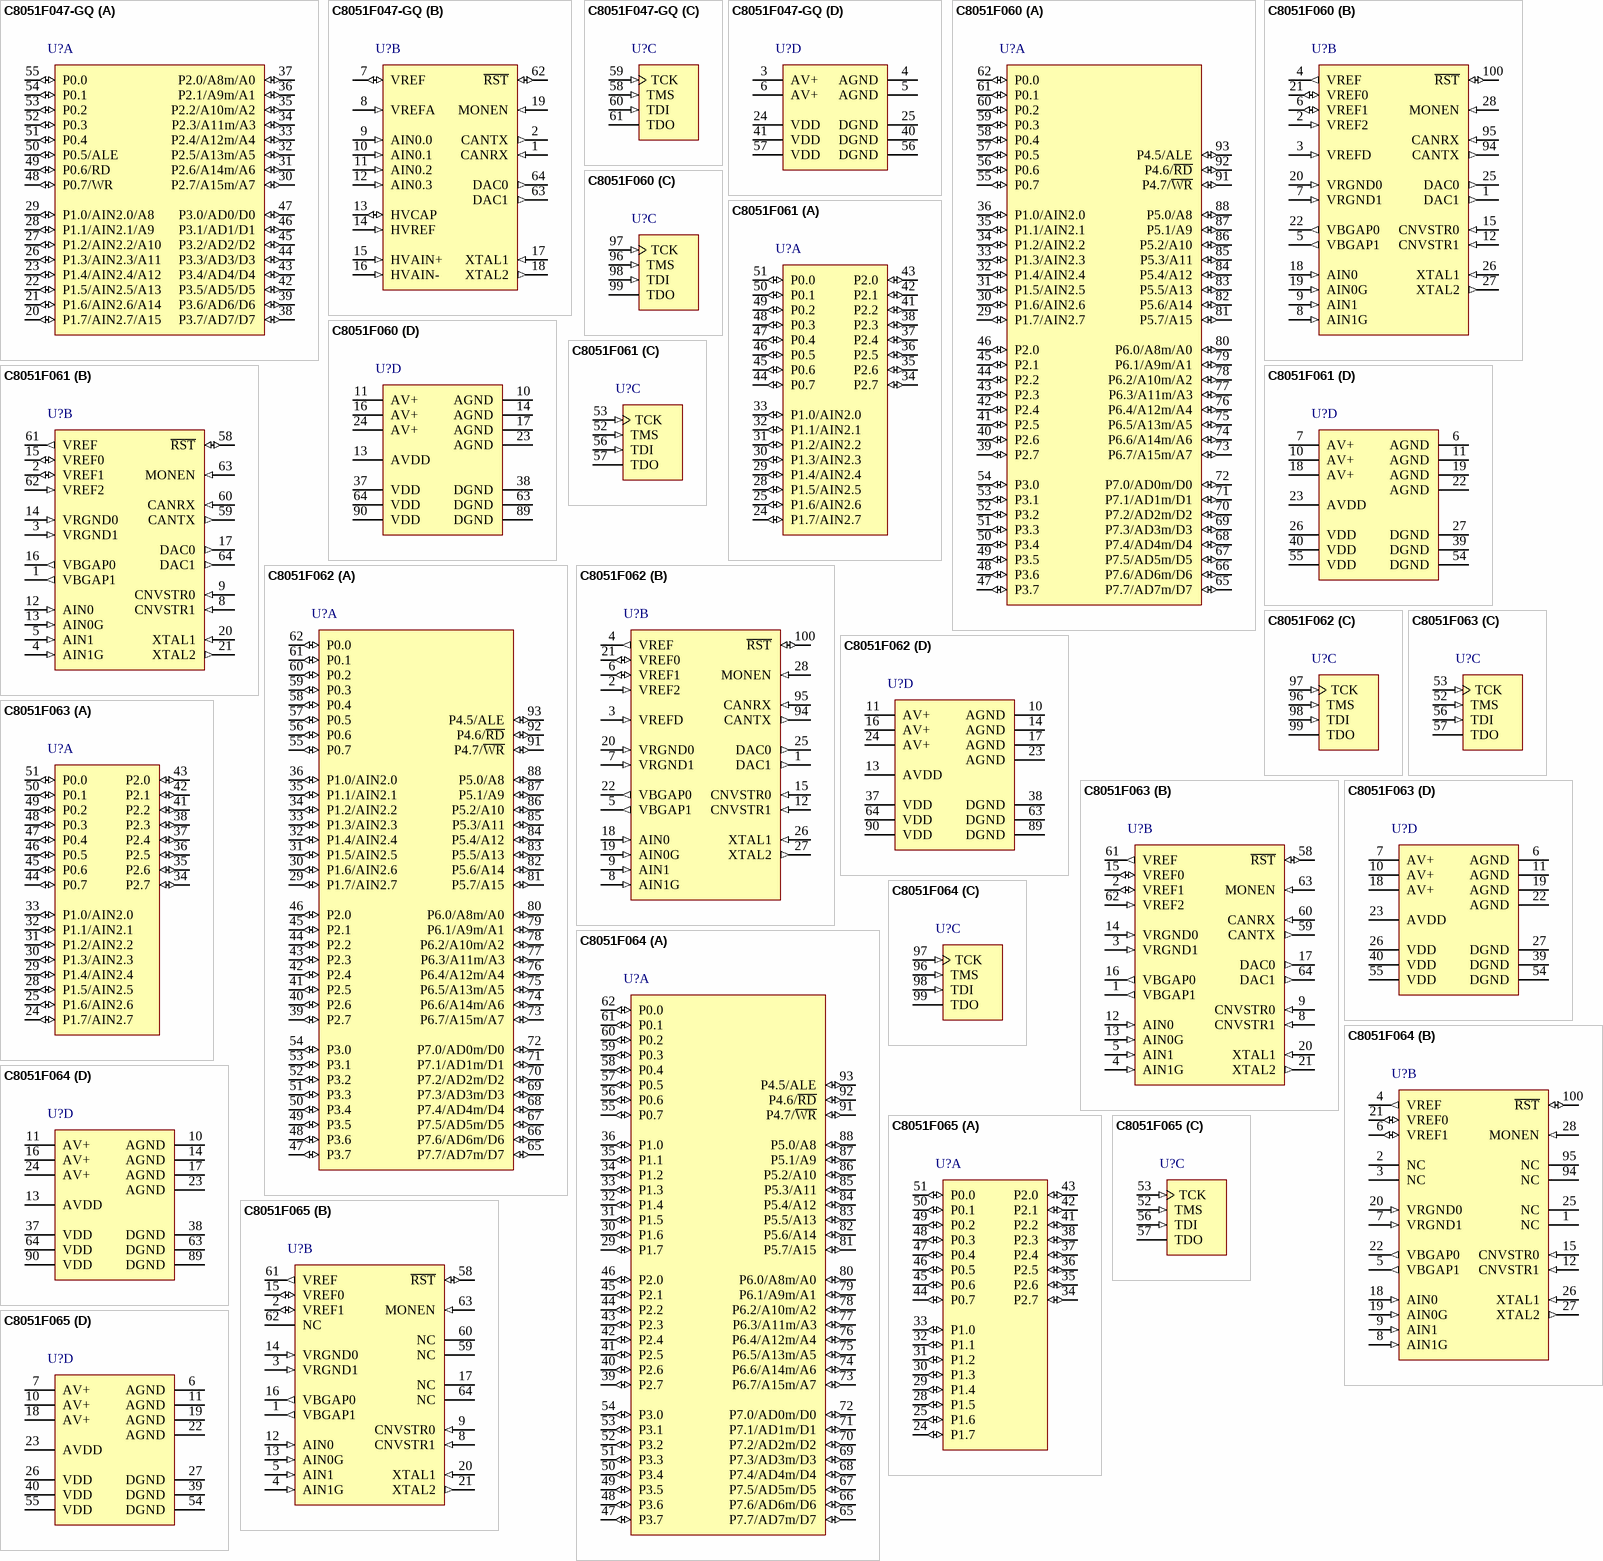
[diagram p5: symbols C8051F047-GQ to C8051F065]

## C8051F047-GQ
designator U?
Mixed Signal 32KB ISP Flash MCU, 25 MIPS, 4352B RAM, 32 I/Os, 10-Bit ADC, 64-Pin TQFP, Pb-Free; Manufacturer: Silicon Labs; PartNumber: C8051F047-GQ
footprint TQFP-64_N (Thin QFP, 64-Leads, Body 10x10mm, Pitch 0.5mm, IPC Medium Density)
footprint TQFP-64_L (Thin QFP, 64-Leads, Body 10x10mm, Pitch 0.5mm, IPC High Density)
footprint TQFP-64_M (Thin QFP, 64-Leads, Body 10x10mm, Pitch 0.5mm, IPC Low Density)
part A pins: 20 P1.7/AIN2.7/A15 (io), 21 P1.6/AIN2.6/A14 (io), 22 P1.5/AIN2.5/A13 (io), 23 P1.4/AIN2.4/A12 (io), 26 P1.3/AIN2.3/A11 (io), 27 P1.2/AIN2.2/A10 (io), 28 P1.1/AIN2.1/A9 (io), 29 P1.0/AIN2.0/A8 (io), 30 P2.7/A15m/A7 (io), 31 P2.6/A14m/A6 (io), 32 P2.5/A13m/A5 (io), 33 P2.4/A12m/A4 (io), 34 P2.3/A11m/A3 (io), 35 P2.2/A10m/A2 (io), 36 P2.1/A9m/A1 (io), 37 P2.0/A8m/A0 (io), 38 P3.7/AD7/D7 (io), 39 P3.6/AD6/D6 (io), 42 P3.5/AD5/D5 (io), 43 P3.4/AD4/D4 (io), 44 P3.3/AD3/D3 (io), 45 P3.2/AD2/D2 (io), 46 P3.1/AD1/D1 (io), 47 P3.0/AD0/D0 (io), 48 P0.7/WR (io), 49 P0.6/RD (io), 50 P0.5/ALE (io), 51 P0.4 (io), 52 P0.3 (io), 53 P0.2 (io), 54 P0.1 (io), 55 P0.0 (io)
part B pins: 1 CANRX (in), 2 CANTX (out), 7 VREF (io), 8 VREFA (in), 9 AIN0.0 (in), 10 AIN0.1 (in), 11 AIN0.2 (in), 12 AIN0.3 (in), 13 HVCAP (io), 14 HVREF (in), 15 HVAIN+ (in), 16 HVAIN- (in), 17 XTAL1 (in), 18 XTAL2 (out), 19 MONEN (in), 62 ~{RST} (io), 63 DAC1 (out), 64 DAC0 (out)
part C pins: 58 TMS (in), 59 TCK (in), 60 TDI (in), 61 TDO (hiz)
part D pins: 3 AV+ (power), 4 AGND (power), 5 AGND (power), 6 AV+ (power), 24 VDD (power), 25 DGND (power), 40 DGND (power), 41 VDD (power), 56 DGND (power), 57 VDD (power)

## C8051F060
designator U?
Mixed Signal 64KB ISP Flash MCU, 25 MIPS, 4352B RAM, 59 I/Os, 16-Bit ADC, 12-Bit DAC, 100-Pin TQFP; Manufacturer: Silicon Labs; PartNumber: C8051F060
footprint TQFP-100_N (Thin QFP, 100-Leads, Body 14x14mm, Pitch 0.5mm, IPC Medium Density)
footprint TQFP-100_L (Thin QFP, 100-Leads, Body 14x14mm, Pitch 0.5mm, IPC High Density)
footprint TQFP-100_M (Thin QFP, 100-Leads, Body 14x14mm, Pitch 0.5mm, IPC Low Density)
part A pins: 29 P1.7/AIN2.7 (io), 30 P1.6/AIN2.6 (io), 31 P1.5/AIN2.5 (io), 32 P1.4/AIN2.4 (io), 33 P1.3/AIN2.3 (io), 34 P1.2/AIN2.2 (io), 35 P1.1/AIN2.1 (io), 36 P1.0/AIN2.0 (io), 39 P2.7 (io), 40 P2.6 (io), 41 P2.5 (io), 42 P2.4 (io), 43 P2.3 (io), 44 P2.2 (io), 45 P2.1 (io), 46 P2.0 (io), 47 P3.7 (io), 48 P3.6 (io), 49 P3.5 (io), 50 P3.4 (io), 51 P3.3 (io), 52 P3.2 (io), 53 P3.1 (io), 54 P3.0 (io), 55 P0.7 (io), 56 P0.6 (io), 57 P0.5 (io), 58 P0.4 (io), 59 P0.3 (io), 60 P0.2 (io), 61 P0.1 (io), 62 P0.0 (io), 65 P7.7/AD7m/D7 (io), 66 P7.6/AD6m/D6 (io), 67 P7.5/AD5m/D5 (io), 68 P7.4/AD4m/D4 (io), 69 P7.3/AD3m/D3 (io), 70 P7.2/AD2m/D2 (io), 71 P7.1/AD1m/D1 (io), 72 P7.0/AD0m/D0 (io), 73 P6.7/A15m/A7 (io), 74 P6.6/A14m/A6 (io), 75 P6.5/A13m/A5 (io), 76 P6.4/A12m/A4 (io), 77 P6.3/A11m/A3 (io), 78 P6.2/A10m/A2 (io), 79 P6.1/A9m/A1 (io), 80 P6.0/A8m/A0 (io), 81 P5.7/A15 (io), 82 P5.6/A14 (io), 83 P5.5/A13 (io), 84 P5.4/A12 (io), 85 P5.3/A11 (io), 86 P5.2/A10 (io), 87 P5.1/A9 (io), 88 P5.0/A8 (io), 91 P4.7/~{WR} (io), 92 P4.6/~{RD} (io), 93 P4.5/ALE (io)
part B pins: 1 DAC1 (out), 2 VREF2 (in), 3 VREFD (in), 4 VREF (out), 5 VBGAP1 (out), 6 VREF1 (io), 7 VRGND1 (in), 8 AIN1G (in), 9 AIN1 (in), 12 CNVSTR1 (in), 15 CNVSTR0 (in), 18 AIN0 (in), 19 AIN0G (in), 20 VRGND0 (in), 21 VREF0 (io), 22 VBGAP0 (out), 25 DAC0 (out), 26 XTAL1 (in), 27 XTAL2 (out), 28 MONEN (in), 94 CANTX (out), 95 CANRX (in), 100 ~{RST} (io)
part C pins: 96 TMS (in), 97 TCK (in), 98 TDI (in), 99 TDO (hiz)
part D pins: 10 AGND (power), 11 AV+ (power), 13 AVDD (power), 14 AGND (power), 16 AV+ (power), 17 AGND (power), 23 AGND (power), 24 AV+ (power), 37 VDD (power), 38 DGND (power), 63 DGND (power), 64 VDD (power), 89 DGND (power), 90 VDD (power)

## C8051F061
designator U?
Mixed Signal 64KB ISP Flash MCU, 25 MIPS, 4352B RAM, 24 I/Os, 16-Bit ADC, 12-Bit DAC, 64-Pin TQFP; Manufacturer: Silicon Labs; PartNumber: C8051F061
footprint TQFP-64_N (Thin QFP, 64-Leads, Body 10x10mm, Pitch 0.5mm, IPC Medium Density)
footprint TQFP-64_L (Thin QFP, 64-Leads, Body 10x10mm, Pitch 0.5mm, IPC High Density)
footprint TQFP-64_M (Thin QFP, 64-Leads, Body 10x10mm, Pitch 0.5mm, IPC Low Density)
part A pins: 24 P1.7/AIN2.7 (io), 25 P1.6/AIN2.6 (io), 28 P1.5/AIN2.5 (io), 29 P1.4/AIN2.4 (io), 30 P1.3/AIN2.3 (io), 31 P1.2/AIN2.2 (io), 32 P1.1/AIN2.1 (io), 33 P1.0/AIN2.0 (io), 34 P2.7 (io), 35 P2.6 (io), 36 P2.5 (io), 37 P2.4 (io), 38 P2.3 (io), 41 P2.2 (io), 42 P2.1 (io), 43 P2.0 (io), 44 P0.7 (io), 45 P0.6 (io), 46 P0.5 (io), 47 P0.4 (io), 48 P0.3 (io), 49 P0.2 (io), 50 P0.1 (io), 51 P0.0 (io)
part B pins: 1 VBGAP1 (out), 2 VREF1 (io), 3 VRGND1 (in), 4 AIN1G (in), 5 AIN1 (in), 8 CNVSTR1 (in), 9 CNVSTR0 (in), 12 AIN0 (in), 13 AIN0G (in), 14 VRGND0 (in), 15 VREF0 (io), 16 VBGAP0 (out), 17 DAC0 (out), 20 XTAL1 (in), 21 XTAL2 (out), 58 ~{RST} (io), 59 CANTX (out), 60 CANRX (in), 61 VREF (out), 62 VREF2 (in), 63 MONEN (in), 64 DAC1 (out)
part C pins: 52 TMS (in), 53 TCK (in), 56 TDI (in), 57 TDO (hiz)
part D pins: 6 AGND (power), 7 AV+ (power), 10 AV+ (power), 11 AGND (power), 18 AV+ (power), 19 AGND (power), 22 AGND (power), 23 AVDD (power), 26 VDD (power), 27 DGND (power), 39 DGND (power), 40 VDD (power), 54 DGND (power), 55 VDD (power)

## C8051F062
designator U?
Mixed Signal 64KB ISP Flash MCU, 25 MIPS, 4352B RAM, 59 I/Os, 16-Bit ADC, 12-Bit DAC, 100-Pin TQFP; Manufacturer: Silicon Labs; PartNumber: C8051F062
footprint TQFP-100_N (Thin QFP, 100-Leads, Body 14x14mm, Pitch 0.5mm, IPC Medium Density)
footprint TQFP-100_L (Thin QFP, 100-Leads, Body 14x14mm, Pitch 0.5mm, IPC High Density)
footprint TQFP-100_M (Thin QFP, 100-Leads, Body 14x14mm, Pitch 0.5mm, IPC Low Density)
part A pins: 29 P1.7/AIN2.7 (io), 30 P1.6/AIN2.6 (io), 31 P1.5/AIN2.5 (io), 32 P1.4/AIN2.4 (io), 33 P1.3/AIN2.3 (io), 34 P1.2/AIN2.2 (io), 35 P1.1/AIN2.1 (io), 36 P1.0/AIN2.0 (io), 39 P2.7 (io), 40 P2.6 (io), 41 P2.5 (io), 42 P2.4 (io), 43 P2.3 (io), 44 P2.2 (io), 45 P2.1 (io), 46 P2.0 (io), 47 P3.7 (io), 48 P3.6 (io), 49 P3.5 (io), 50 P3.4 (io), 51 P3.3 (io), 52 P3.2 (io), 53 P3.1 (io), 54 P3.0 (io), 55 P0.7 (io), 56 P0.6 (io), 57 P0.5 (io), 58 P0.4 (io), 59 P0.3 (io), 60 P0.2 (io), 61 P0.1 (io), 62 P0.0 (io), 65 P7.7/AD7m/D7 (io), 66 P7.6/AD6m/D6 (io), 67 P7.5/AD5m/D5 (io), 68 P7.4/AD4m/D4 (io), 69 P7.3/AD3m/D3 (io), 70 P7.2/AD2m/D2 (io), 71 P7.1/AD1m/D1 (io), 72 P7.0/AD0m/D0 (io), 73 P6.7/A15m/A7 (io), 74 P6.6/A14m/A6 (io), 75 P6.5/A13m/A5 (io), 76 P6.4/A12m/A4 (io), 77 P6.3/A11m/A3 (io), 78 P6.2/A10m/A2 (io), 79 P6.1/A9m/A1 (io), 80 P6.0/A8m/A0 (io), 81 P5.7/A15 (io), 82 P5.6/A14 (io), 83 P5.5/A13 (io), 84 P5.4/A12 (io), 85 P5.3/A11 (io), 86 P5.2/A10 (io), 87 P5.1/A9 (io), 88 P5.0/A8 (io), 91 P4.7/~{WR} (io), 92 P4.6/~{RD} (io), 93 P4.5/ALE (io)
part B pins: 1 DAC1 (out), 2 VREF2 (in), 3 VREFD (in), 4 VREF (out), 5 VBGAP1 (out), 6 VREF1 (io), 7 VRGND1 (in), 8 AIN1G (in), 9 AIN1 (in), 12 CNVSTR1 (in), 15 CNVSTR0 (in), 18 AIN0 (in), 19 AIN0G (in), 20 VRGND0 (in), 21 VREF0 (io), 22 VBGAP0 (out), 25 DAC0 (out), 26 XTAL1 (in), 27 XTAL2 (out), 28 MONEN (in), 94 CANTX (out), 95 CANRX (in), 100 ~{RST} (io)
part C pins: 96 TMS (in), 97 TCK (in), 98 TDI (in), 99 TDO (hiz)
part D pins: 10 AGND (power), 11 AV+ (power), 13 AVDD (power), 14 AGND (power), 16 AV+ (power), 17 AGND (power), 23 AGND (power), 24 AV+ (power), 37 VDD (power), 38 DGND (power), 63 DGND (power), 64 VDD (power), 89 DGND (power), 90 VDD (power)

## C8051F063
designator U?
Mixed Signal 64KB ISP Flash MCU, 25 MIPS, 4352B RAM, 24 I/Os, 16-Bit ADC, 12-Bit DAC, 64-Pin TQFP; Manufacturer: Silicon Labs; PartNumber: C8051F063
footprint TQFP-64_N (Thin QFP, 64-Leads, Body 10x10mm, Pitch 0.5mm, IPC Medium Density)
footprint TQFP-64_L (Thin QFP, 64-Leads, Body 10x10mm, Pitch 0.5mm, IPC High Density)
footprint TQFP-64_M (Thin QFP, 64-Leads, Body 10x10mm, Pitch 0.5mm, IPC Low Density)
part A pins: 24 P1.7/AIN2.7 (io), 25 P1.6/AIN2.6 (io), 28 P1.5/AIN2.5 (io), 29 P1.4/AIN2.4 (io), 30 P1.3/AIN2.3 (io), 31 P1.2/AIN2.2 (io), 32 P1.1/AIN2.1 (io), 33 P1.0/AIN2.0 (io), 34 P2.7 (io), 35 P2.6 (io), 36 P2.5 (io), 37 P2.4 (io), 38 P2.3 (io), 41 P2.2 (io), 42 P2.1 (io), 43 P2.0 (io), 44 P0.7 (io), 45 P0.6 (io), 46 P0.5 (io), 47 P0.4 (io), 48 P0.3 (io), 49 P0.2 (io), 50 P0.1 (io), 51 P0.0 (io)
part B pins: 1 VBGAP1 (out), 2 VREF1 (io), 3 VRGND1 (in), 4 AIN1G (in), 5 AIN1 (in), 8 CNVSTR1 (in), 9 CNVSTR0 (in), 12 AIN0 (in), 13 AIN0G (in), 14 VRGND0 (in), 15 VREF0 (io), 16 VBGAP0 (out), 17 DAC0 (out), 20 XTAL1 (in), 21 XTAL2 (out), 58 ~{RST} (io), 59 CANTX (out), 60 CANRX (in), 61 VREF (out), 62 VREF2 (in), 63 MONEN (in), 64 DAC1 (out)
part C pins: 52 TMS (in), 53 TCK (in), 56 TDI (in), 57 TDO (hiz)
part D pins: 6 AGND (power), 7 AV+ (power), 10 AV+ (power), 11 AGND (power), 18 AV+ (power), 19 AGND (power), 22 AGND (power), 23 AVDD (power), 26 VDD (power), 27 DGND (power), 39 DGND (power), 40 VDD (power), 54 DGND (power), 55 VDD (power)

## C8051F064
designator U?
Mixed Signal 64KB ISP Flash MCU, 25 MIPS, 4352B RAM, 59 I/Os, 16-Bit ADC, 100-Pin TQFP; Manufacturer: Silicon Labs; PartNumber: C8051F064
footprint TQFP-100_N (Thin QFP, 100-Leads, Body 14x14mm, Pitch 0.5mm, IPC Medium Density)
footprint TQFP-100_L (Thin QFP, 100-Leads, Body 14x14mm, Pitch 0.5mm, IPC High Density)
footprint TQFP-100_M (Thin QFP, 100-Leads, Body 14x14mm, Pitch 0.5mm, IPC Low Density)
part A pins: 29 P1.7 (io), 30 P1.6 (io), 31 P1.5 (io), 32 P1.4 (io), 33 P1.3 (io), 34 P1.2 (io), 35 P1.1 (io), 36 P1.0 (io), 39 P2.7 (io), 40 P2.6 (io), 41 P2.5 (io), 42 P2.4 (io), 43 P2.3 (io), 44 P2.2 (io), 45 P2.1 (io), 46 P2.0 (io), 47 P3.7 (io), 48 P3.6 (io), 49 P3.5 (io), 50 P3.4 (io), 51 P3.3 (io), 52 P3.2 (io), 53 P3.1 (io), 54 P3.0 (io), 55 P0.7 (io), 56 P0.6 (io), 57 P0.5 (io), 58 P0.4 (io), 59 P0.3 (io), 60 P0.2 (io), 61 P0.1 (io), 62 P0.0 (io), 65 P7.7/AD7m/D7 (io), 66 P7.6/AD6m/D6 (io), 67 P7.5/AD5m/D5 (io), 68 P7.4/AD4m/D4 (io), 69 P7.3/AD3m/D3 (io), 70 P7.2/AD2m/D2 (io), 71 P7.1/AD1m/D1 (io), 72 P7.0/AD0m/D0 (io), 73 P6.7/A15m/A7 (io), 74 P6.6/A14m/A6 (io), 75 P6.5/A13m/A5 (io), 76 P6.4/A12m/A4 (io), 77 P6.3/A11m/A3 (io), 78 P6.2/A10m/A2 (io), 79 P6.1/A9m/A1 (io), 80 P6.0/A8m/A0 (io), 81 P5.7/A15 (io), 82 P5.6/A14 (io), 83 P5.5/A13 (io), 84 P5.4/A12 (io), 85 P5.3/A11 (io), 86 P5.2/A10 (io), 87 P5.1/A9 (io), 88 P5.0/A8 (io), 91 P4.7/~{WR} (io), 92 P4.6/~{RD} (io), 93 P4.5/ALE (io)
part B pins: 1 NC, 2 NC, 3 NC, 4 VREF (out), 5 VBGAP1 (out), 6 VREF1 (io), 7 VRGND1 (in), 8 AIN1G (in), 9 AIN1 (in), 12 CNVSTR1 (in), 15 CNVSTR0 (in), 18 AIN0 (in), 19 AIN0G (in), 20 VRGND0 (in), 21 VREF0 (io), 22 VBGAP0 (out), 25 NC, 26 XTAL1 (in), 27 XTAL2 (out), 28 MONEN (in), 94 NC, 95 NC, 100 ~{RST} (io)
part C pins: 96 TMS (in), 97 TCK (in), 98 TDI (in), 99 TDO (hiz)
part D pins: 10 AGND (power), 11 AV+ (power), 13 AVDD (power), 14 AGND (power), 16 AV+ (power), 17 AGND (power), 23 AGND (power), 24 AV+ (power), 37 VDD (power), 38 DGND (power), 63 DGND (power), 64 VDD (power), 89 DGND (power), 90 VDD (power)

## C8051F065
designator U?
Mixed Signal 64KB ISP Flash MCU, 25 MIPS, 4352B RAM, 24 I/Os, 16-Bit ADC, 64-Pin TQFP; Manufacturer: Silicon Labs; PartNumber: C8051F065
footprint TQFP-64_N (Thin QFP, 64-Leads, Body 10x10mm, Pitch 0.5mm, IPC Medium Density)
footprint TQFP-64_L (Thin QFP, 64-Leads, Body 10x10mm, Pitch 0.5mm, IPC High Density)
footprint TQFP-64_M (Thin QFP, 64-Leads, Body 10x10mm, Pitch 0.5mm, IPC Low Density)
part A pins: 24 P1.7 (io), 25 P1.6 (io), 28 P1.5 (io), 29 P1.4 (io), 30 P1.3 (io), 31 P1.2 (io), 32 P1.1 (io), 33 P1.0 (io), 34 P2.7 (io), 35 P2.6 (io), 36 P2.5 (io), 37 P2.4 (io), 38 P2.3 (io), 41 P2.2 (io), 42 P2.1 (io), 43 P2.0 (io), 44 P0.7 (io), 45 P0.6 (io), 46 P0.5 (io), 47 P0.4 (io), 48 P0.3 (io), 49 P0.2 (io), 50 P0.1 (io), 51 P0.0 (io)
part B pins: 1 VBGAP1 (out), 2 VREF1 (io), 3 VRGND1 (in), 4 AIN1G (in), 5 AIN1 (in), 8 CNVSTR1 (in), 9 CNVSTR0 (in), 12 AIN0 (in), 13 AIN0G (in), 14 VRGND0 (in), 15 VREF0 (io), 16 VBGAP0 (out), 17 NC, 20 XTAL1 (in), 21 XTAL2 (out), 58 ~{RST} (io), 59 NC, 60 NC, 61 VREF (out), 62 NC, 63 MONEN (in), 64 NC
part C pins: 52 TMS (in), 53 TCK (in), 56 TDI (in), 57 TDO (hiz)
part D pins: 6 AGND (power), 7 AV+ (power), 10 AV+ (power), 11 AGND (power), 18 AV+ (power), 19 AGND (power), 22 AGND (power), 23 AVDD (power), 26 VDD (power), 27 DGND (power), 39 DGND (power), 40 VDD (power), 54 DGND (power), 55 VDD (power)

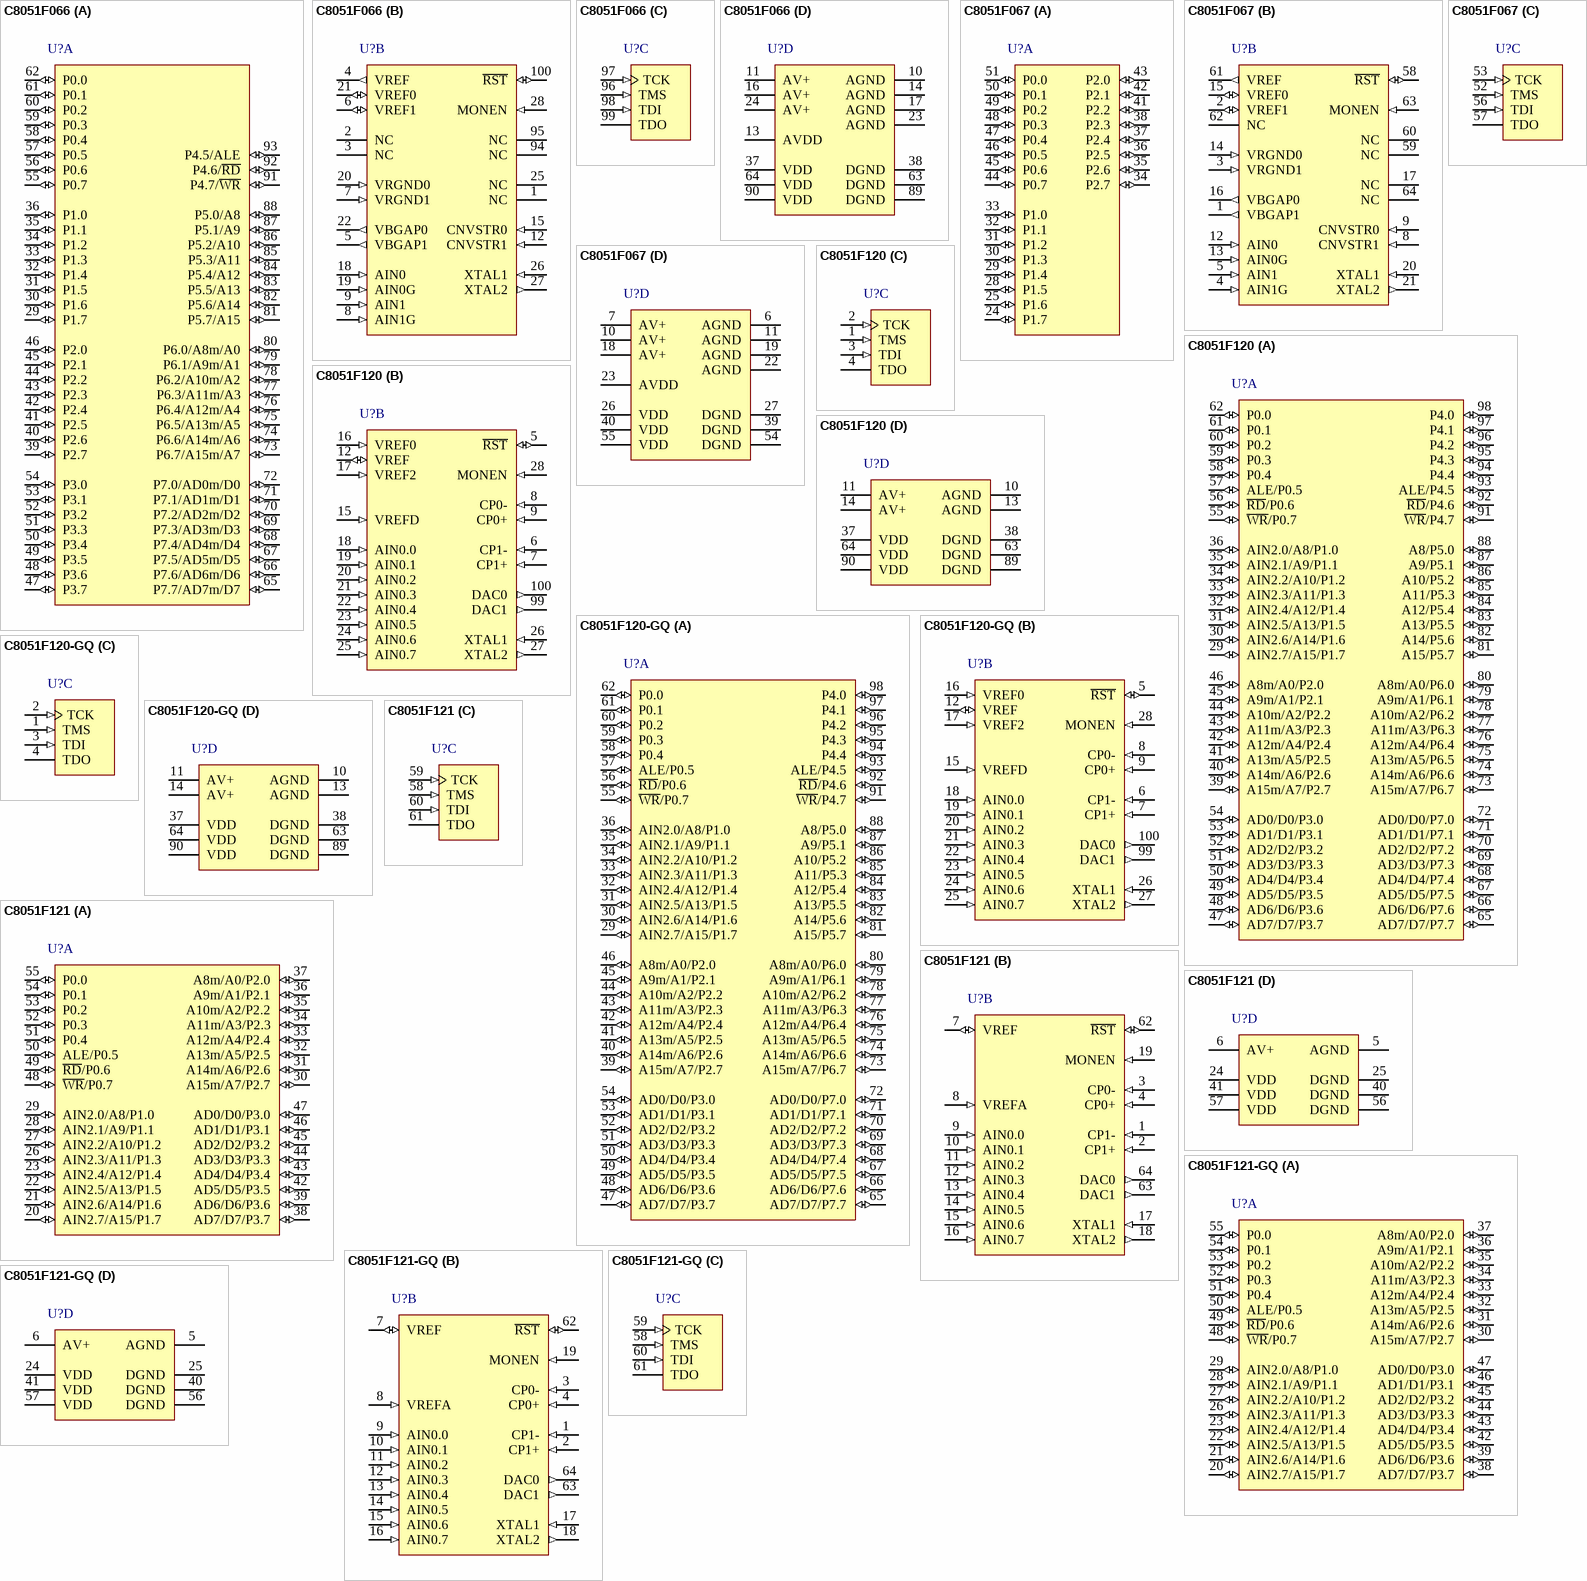
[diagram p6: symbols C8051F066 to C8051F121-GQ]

## C8051F066
designator U?
Mixed Signal 32KB ISP Flash MCU, 25 MIPS, 4352B RAM, 59 I/Os, 16-Bit ADC, 100-Pin TQFP; Manufacturer: Silicon Labs; PartNumber: C8051F066
footprint TQFP-100_N (Thin QFP, 100-Leads, Body 14x14mm, Pitch 0.5mm, IPC Medium Density)
footprint TQFP-100_L (Thin QFP, 100-Leads, Body 14x14mm, Pitch 0.5mm, IPC High Density)
footprint TQFP-100_M (Thin QFP, 100-Leads, Body 14x14mm, Pitch 0.5mm, IPC Low Density)
part A pins: 29 P1.7 (io), 30 P1.6 (io), 31 P1.5 (io), 32 P1.4 (io), 33 P1.3 (io), 34 P1.2 (io), 35 P1.1 (io), 36 P1.0 (io), 39 P2.7 (io), 40 P2.6 (io), 41 P2.5 (io), 42 P2.4 (io), 43 P2.3 (io), 44 P2.2 (io), 45 P2.1 (io), 46 P2.0 (io), 47 P3.7 (io), 48 P3.6 (io), 49 P3.5 (io), 50 P3.4 (io), 51 P3.3 (io), 52 P3.2 (io), 53 P3.1 (io), 54 P3.0 (io), 55 P0.7 (io), 56 P0.6 (io), 57 P0.5 (io), 58 P0.4 (io), 59 P0.3 (io), 60 P0.2 (io), 61 P0.1 (io), 62 P0.0 (io), 65 P7.7/AD7m/D7 (io), 66 P7.6/AD6m/D6 (io), 67 P7.5/AD5m/D5 (io), 68 P7.4/AD4m/D4 (io), 69 P7.3/AD3m/D3 (io), 70 P7.2/AD2m/D2 (io), 71 P7.1/AD1m/D1 (io), 72 P7.0/AD0m/D0 (io), 73 P6.7/A15m/A7 (io), 74 P6.6/A14m/A6 (io), 75 P6.5/A13m/A5 (io), 76 P6.4/A12m/A4 (io), 77 P6.3/A11m/A3 (io), 78 P6.2/A10m/A2 (io), 79 P6.1/A9m/A1 (io), 80 P6.0/A8m/A0 (io), 81 P5.7/A15 (io), 82 P5.6/A14 (io), 83 P5.5/A13 (io), 84 P5.4/A12 (io), 85 P5.3/A11 (io), 86 P5.2/A10 (io), 87 P5.1/A9 (io), 88 P5.0/A8 (io), 91 P4.7/~{WR} (io), 92 P4.6/~{RD} (io), 93 P4.5/ALE (io)
part B pins: 1 NC, 2 NC, 3 NC, 4 VREF (out), 5 VBGAP1 (out), 6 VREF1 (io), 7 VRGND1 (in), 8 AIN1G (in), 9 AIN1 (in), 12 CNVSTR1 (in), 15 CNVSTR0 (in), 18 AIN0 (in), 19 AIN0G (in), 20 VRGND0 (in), 21 VREF0 (io), 22 VBGAP0 (out), 25 NC, 26 XTAL1 (in), 27 XTAL2 (out), 28 MONEN (in), 94 NC, 95 NC, 100 ~{RST} (io)
part C pins: 96 TMS (in), 97 TCK (in), 98 TDI (in), 99 TDO (hiz)
part D pins: 10 AGND (power), 11 AV+ (power), 13 AVDD (power), 14 AGND (power), 16 AV+ (power), 17 AGND (power), 23 AGND (power), 24 AV+ (power), 37 VDD (power), 38 DGND (power), 63 DGND (power), 64 VDD (power), 89 DGND (power), 90 VDD (power)

## C8051F067
designator U?
Mixed Signal 32KB ISP Flash MCU, 25 MIPS, 4352B RAM, 24 I/Os, 16-Bit ADC, 64-Pin TQFP; Manufacturer: Silicon Labs; PartNumber: C8051F067
footprint TQFP-64_N (Thin QFP, 64-Leads, Body 10x10mm, Pitch 0.5mm, IPC Medium Density)
footprint TQFP-64_L (Thin QFP, 64-Leads, Body 10x10mm, Pitch 0.5mm, IPC High Density)
footprint TQFP-64_M (Thin QFP, 64-Leads, Body 10x10mm, Pitch 0.5mm, IPC Low Density)
part A pins: 24 P1.7 (io), 25 P1.6 (io), 28 P1.5 (io), 29 P1.4 (io), 30 P1.3 (io), 31 P1.2 (io), 32 P1.1 (io), 33 P1.0 (io), 34 P2.7 (io), 35 P2.6 (io), 36 P2.5 (io), 37 P2.4 (io), 38 P2.3 (io), 41 P2.2 (io), 42 P2.1 (io), 43 P2.0 (io), 44 P0.7 (io), 45 P0.6 (io), 46 P0.5 (io), 47 P0.4 (io), 48 P0.3 (io), 49 P0.2 (io), 50 P0.1 (io), 51 P0.0 (io)
part B pins: 1 VBGAP1 (out), 2 VREF1 (io), 3 VRGND1 (in), 4 AIN1G (in), 5 AIN1 (in), 8 CNVSTR1 (in), 9 CNVSTR0 (in), 12 AIN0 (in), 13 AIN0G (in), 14 VRGND0 (in), 15 VREF0 (io), 16 VBGAP0 (out), 17 NC, 20 XTAL1 (in), 21 XTAL2 (out), 58 ~{RST} (io), 59 NC, 60 NC, 61 VREF (out), 62 NC, 63 MONEN (in), 64 NC
part C pins: 52 TMS (in), 53 TCK (in), 56 TDI (in), 57 TDO (hiz)
part D pins: 6 AGND (power), 7 AV+ (power), 10 AV+ (power), 11 AGND (power), 18 AV+ (power), 19 AGND (power), 22 AGND (power), 23 AVDD (power), 26 VDD (power), 27 DGND (power), 39 DGND (power), 40 VDD (power), 54 DGND (power), 55 VDD (power)

## C8051F120
designator U?
Mixed Signal 128KB ISP Flash MCU, 100 MIPS, 8448B RAM, 64 I/Os, 12-Bit & 8-Bit ADC, 12-Bit DAC, 100-Pin TQFP; Manufacturer: Silicon Labs; PartNumber: C8051F120
footprint TQFP-100_N (Thin QFP, 100-Leads, Body 14x14mm, Pitch 0.5mm, IPC Medium Density)
footprint TQFP-100_L (Thin QFP, 100-Leads, Body 14x14mm, Pitch 0.5mm, IPC High Density)
footprint TQFP-100_M (Thin QFP, 100-Leads, Body 14x14mm, Pitch 0.5mm, IPC Low Density)
part A pins: 29 AIN2.7/A15/P1.7 (io), 30 AIN2.6/A14/P1.6 (io), 31 AIN2.5/A13/P1.5 (io), 32 AIN2.4/A12/P1.4 (io), 33 AIN2.3/A11/P1.3 (io), 34 AIN2.2/A10/P1.2 (io), 35 AIN2.1/A9/P1.1 (io), 36 AIN2.0/A8/P1.0 (io), 39 A15m/A7/P2.7 (io), 40 A14m/A6/P2.6 (io), 41 A13m/A5/P2.5 (io), 42 A12m/A4/P2.4 (io), 43 A11m/A3/P2.3 (io), 44 A10m/A2/P2.2 (io), 45 A9m/A1/P2.1 (io), 46 A8m/A0/P2.0 (io), 47 AD7/D7/P3.7 (io), 48 AD6/D6/P3.6 (io), 49 AD5/D5/P3.5 (io), 50 AD4/D4/P3.4 (io), 51 AD3/D3/P3.3 (io), 52 AD2/D2/P3.2 (io), 53 AD1/D1/P3.1 (io), 54 AD0/D0/P3.0 (io), 55 ~{WR}/P0.7 (io), 56 ~{RD}/P0.6 (io), 57 ALE/P0.5 (io), 58 P0.4 (io), 59 P0.3 (io), 60 P0.2 (io), 61 P0.1 (io), 62 P0.0 (io), 65 AD7/D7/P7.7 (io), 66 AD6/D6/P7.6 (io), 67 AD5/D5/P7.5 (io), 68 AD4/D4/P7.4 (io), 69 AD3/D3/P7.3 (io), 70 AD2/D2/P7.2 (io), 71 AD1/D1/P7.1 (io), 72 AD0/D0/P7.0 (io), 73 A15m/A7/P6.7 (io), 74 A14m/A6/P6.6 (io), 75 A13m/A5/P6.5 (io), 76 A12m/A4/P6.4 (io), 77 A11m/A3/P6.3 (io), 78 A10m/A2/P6.2 (io), 79 A9m/A1/P6.1 (io), 80 A8m/A0/P6.0 (io), 81 A15/P5.7 (io), 82 A14/P5.6 (io), 83 A13/P5.5 (io), 84 A12/P5.4 (io), 85 A11/P5.3 (io), 86 A10/P5.2 (io), 87 A9/P5.1 (io), 88 A8/P5.0 (io), 91 ~{WR}/P4.7 (io), 92 ~{RD}/P4.6 (io), 93 ALE/P4.5 (io), 94 P4.4 (io), 95 P4.3 (io), 96 P4.2 (io), 97 P4.1 (io), 98 P4.0 (io)
part B pins: 5 ~{RST} (io), 6 CP1- (in), 7 CP1+ (in), 8 CP0- (in), 9 CP0+ (in), 12 VREF (io), 15 VREFD (in), 16 VREF0 (in), 17 VREF2 (in), 18 AIN0.0 (in), 19 AIN0.1 (in), 20 AIN0.2 (in), 21 AIN0.3 (in), 22 AIN0.4 (in), 23 AIN0.5 (in), 24 AIN0.6 (in), 25 AIN0.7 (in), 26 XTAL1 (in), 27 XTAL2 (out), 28 MONEN (in), 99 DAC1 (out), 100 DAC0 (out)
part C pins: 1 TMS (in), 2 TCK (in), 3 TDI (in), 4 TDO (hiz)
part D pins: 10 AGND (power), 11 AV+ (power), 13 AGND (power), 14 AV+ (power), 37 VDD (power), 38 DGND (power), 63 DGND (power), 64 VDD (power), 89 DGND (power), 90 VDD (power)

## C8051F120-GQ
designator U?
Mixed Signal 128KB ISP Flash MCU, 100 MIPS, 8448B RAM, 64 I/Os, 12-Bit & 8-Bit ADC, 12-Bit DAC, 100-Pin TQFP, Pb-Free; Manufacturer: Silicon Labs; PartNumber: C8051F120-GQ
footprint TQFP-100_N (Thin QFP, 100-Leads, Body 14x14mm, Pitch 0.5mm, IPC Medium Density)
footprint TQFP-100_L (Thin QFP, 100-Leads, Body 14x14mm, Pitch 0.5mm, IPC High Density)
footprint TQFP-100_M (Thin QFP, 100-Leads, Body 14x14mm, Pitch 0.5mm, IPC Low Density)
part A pins: 29 AIN2.7/A15/P1.7 (io), 30 AIN2.6/A14/P1.6 (io), 31 AIN2.5/A13/P1.5 (io), 32 AIN2.4/A12/P1.4 (io), 33 AIN2.3/A11/P1.3 (io), 34 AIN2.2/A10/P1.2 (io), 35 AIN2.1/A9/P1.1 (io), 36 AIN2.0/A8/P1.0 (io), 39 A15m/A7/P2.7 (io), 40 A14m/A6/P2.6 (io), 41 A13m/A5/P2.5 (io), 42 A12m/A4/P2.4 (io), 43 A11m/A3/P2.3 (io), 44 A10m/A2/P2.2 (io), 45 A9m/A1/P2.1 (io), 46 A8m/A0/P2.0 (io), 47 AD7/D7/P3.7 (io), 48 AD6/D6/P3.6 (io), 49 AD5/D5/P3.5 (io), 50 AD4/D4/P3.4 (io), 51 AD3/D3/P3.3 (io), 52 AD2/D2/P3.2 (io), 53 AD1/D1/P3.1 (io), 54 AD0/D0/P3.0 (io), 55 ~{WR}/P0.7 (io), 56 ~{RD}/P0.6 (io), 57 ALE/P0.5 (io), 58 P0.4 (io), 59 P0.3 (io), 60 P0.2 (io), 61 P0.1 (io), 62 P0.0 (io), 65 AD7/D7/P7.7 (io), 66 AD6/D6/P7.6 (io), 67 AD5/D5/P7.5 (io), 68 AD4/D4/P7.4 (io), 69 AD3/D3/P7.3 (io), 70 AD2/D2/P7.2 (io), 71 AD1/D1/P7.1 (io), 72 AD0/D0/P7.0 (io), 73 A15m/A7/P6.7 (io), 74 A14m/A6/P6.6 (io), 75 A13m/A5/P6.5 (io), 76 A12m/A4/P6.4 (io), 77 A11m/A3/P6.3 (io), 78 A10m/A2/P6.2 (io), 79 A9m/A1/P6.1 (io), 80 A8m/A0/P6.0 (io), 81 A15/P5.7 (io), 82 A14/P5.6 (io), 83 A13/P5.5 (io), 84 A12/P5.4 (io), 85 A11/P5.3 (io), 86 A10/P5.2 (io), 87 A9/P5.1 (io), 88 A8/P5.0 (io), 91 ~{WR}/P4.7 (io), 92 ~{RD}/P4.6 (io), 93 ALE/P4.5 (io), 94 P4.4 (io), 95 P4.3 (io), 96 P4.2 (io), 97 P4.1 (io), 98 P4.0 (io)
part B pins: 5 ~{RST} (io), 6 CP1- (in), 7 CP1+ (in), 8 CP0- (in), 9 CP0+ (in), 12 VREF (io), 15 VREFD (in), 16 VREF0 (in), 17 VREF2 (in), 18 AIN0.0 (in), 19 AIN0.1 (in), 20 AIN0.2 (in), 21 AIN0.3 (in), 22 AIN0.4 (in), 23 AIN0.5 (in), 24 AIN0.6 (in), 25 AIN0.7 (in), 26 XTAL1 (in), 27 XTAL2 (out), 28 MONEN (in), 99 DAC1 (out), 100 DAC0 (out)
part C pins: 1 TMS (in), 2 TCK (in), 3 TDI (in), 4 TDO (hiz)
part D pins: 10 AGND (power), 11 AV+ (power), 13 AGND (power), 14 AV+ (power), 37 VDD (power), 38 DGND (power), 63 DGND (power), 64 VDD (power), 89 DGND (power), 90 VDD (power)

## C8051F121
designator U?
Mixed Signal 128KB ISP Flash MCU, 100 MIPS, 8448B RAM, 32 I/Os, 12-Bit & 8-Bit ADC, 12-Bit DAC, 64-Pin TQFP; Manufacturer: Silicon Labs; PartNumber: C8051F121
footprint TQFP-64_N (Thin QFP, 64-Leads, Body 10x10mm, Pitch 0.5mm, IPC Medium Density)
footprint TQFP-64_L (Thin QFP, 64-Leads, Body 10x10mm, Pitch 0.5mm, IPC High Density)
footprint TQFP-64_M (Thin QFP, 64-Leads, Body 10x10mm, Pitch 0.5mm, IPC Low Density)
part A pins: 20 AIN2.7/A15/P1.7 (io), 21 AIN2.6/A14/P1.6 (io), 22 AIN2.5/A13/P1.5 (io), 23 AIN2.4/A12/P1.4 (io), 26 AIN2.3/A11/P1.3 (io), 27 AIN2.2/A10/P1.2 (io), 28 AIN2.1/A9/P1.1 (io), 29 AIN2.0/A8/P1.0 (io), 30 A15m/A7/P2.7 (io), 31 A14m/A6/P2.6 (io), 32 A13m/A5/P2.5 (io), 33 A12m/A4/P2.4 (io), 34 A11m/A3/P2.3 (io), 35 A10m/A2/P2.2 (io), 36 A9m/A1/P2.1 (io), 37 A8m/A0/P2.0 (io), 38 AD7/D7/P3.7 (io), 39 AD6/D6/P3.6 (io), 42 AD5/D5/P3.5 (io), 43 AD4/D4/P3.4 (io), 44 AD3/D3/P3.3 (io), 45 AD2/D2/P3.2 (io), 46 AD1/D1/P3.1 (io), 47 AD0/D0/P3.0 (io), 48 ~{WR}/P0.7 (io), 49 ~{RD}/P0.6 (io), 50 ALE/P0.5 (io), 51 P0.4 (io), 52 P0.3 (io), 53 P0.2 (io), 54 P0.1 (io), 55 P0.0 (io)
part B pins: 1 CP1- (in), 2 CP1+ (in), 3 CP0- (in), 4 CP0+ (in), 7 VREF (io), 8 VREFA (in), 9 AIN0.0 (in), 10 AIN0.1 (in), 11 AIN0.2 (in), 12 AIN0.3 (in), 13 AIN0.4 (in), 14 AIN0.5 (in), 15 AIN0.6 (in), 16 AIN0.7 (in), 17 XTAL1 (in), 18 XTAL2 (out), 19 MONEN (in), 62 ~{RST} (io), 63 DAC1 (out), 64 DAC0 (out)
part C pins: 58 TMS (in), 59 TCK (in), 60 TDI (in), 61 TDO (hiz)
part D pins: 5 AGND (power), 6 AV+ (power), 24 VDD (power), 25 DGND (power), 40 DGND (power), 41 VDD (power), 56 DGND (power), 57 VDD (power)

## C8051F121-GQ
designator U?
Mixed Signal 128KB ISP Flash MCU, 100 MIPS, 8448B RAM, 32 I/Os, 12-Bit & 8-Bit ADC, 12-Bit DAC, 64-Pin TQFP, Pb-Free; Manufacturer: Silicon Labs; PartNumber: C8051F121-GQ
footprint TQFP-64_N (Thin QFP, 64-Leads, Body 10x10mm, Pitch 0.5mm, IPC Medium Density)
footprint TQFP-64_L (Thin QFP, 64-Leads, Body 10x10mm, Pitch 0.5mm, IPC High Density)
footprint TQFP-64_M (Thin QFP, 64-Leads, Body 10x10mm, Pitch 0.5mm, IPC Low Density)
part A pins: 20 AIN2.7/A15/P1.7 (io), 21 AIN2.6/A14/P1.6 (io), 22 AIN2.5/A13/P1.5 (io), 23 AIN2.4/A12/P1.4 (io), 26 AIN2.3/A11/P1.3 (io), 27 AIN2.2/A10/P1.2 (io), 28 AIN2.1/A9/P1.1 (io), 29 AIN2.0/A8/P1.0 (io), 30 A15m/A7/P2.7 (io), 31 A14m/A6/P2.6 (io), 32 A13m/A5/P2.5 (io), 33 A12m/A4/P2.4 (io), 34 A11m/A3/P2.3 (io), 35 A10m/A2/P2.2 (io), 36 A9m/A1/P2.1 (io), 37 A8m/A0/P2.0 (io), 38 AD7/D7/P3.7 (io), 39 AD6/D6/P3.6 (io), 42 AD5/D5/P3.5 (io), 43 AD4/D4/P3.4 (io), 44 AD3/D3/P3.3 (io), 45 AD2/D2/P3.2 (io), 46 AD1/D1/P3.1 (io), 47 AD0/D0/P3.0 (io), 48 ~{WR}/P0.7 (io), 49 ~{RD}/P0.6 (io), 50 ALE/P0.5 (io), 51 P0.4 (io), 52 P0.3 (io), 53 P0.2 (io), 54 P0.1 (io), 55 P0.0 (io)
part B pins: 1 CP1- (in), 2 CP1+ (in), 3 CP0- (in), 4 CP0+ (in), 7 VREF (io), 8 VREFA (in), 9 AIN0.0 (in), 10 AIN0.1 (in), 11 AIN0.2 (in), 12 AIN0.3 (in), 13 AIN0.4 (in), 14 AIN0.5 (in), 15 AIN0.6 (in), 16 AIN0.7 (in), 17 XTAL1 (in), 18 XTAL2 (out), 19 MONEN (in), 62 ~{RST} (io), 63 DAC1 (out), 64 DAC0 (out)
part C pins: 58 TMS (in), 59 TCK (in), 60 TDI (in), 61 TDO (hiz)
part D pins: 5 AGND (power), 6 AV+ (power), 24 VDD (power), 25 DGND (power), 40 DGND (power), 41 VDD (power), 56 DGND (power), 57 VDD (power)

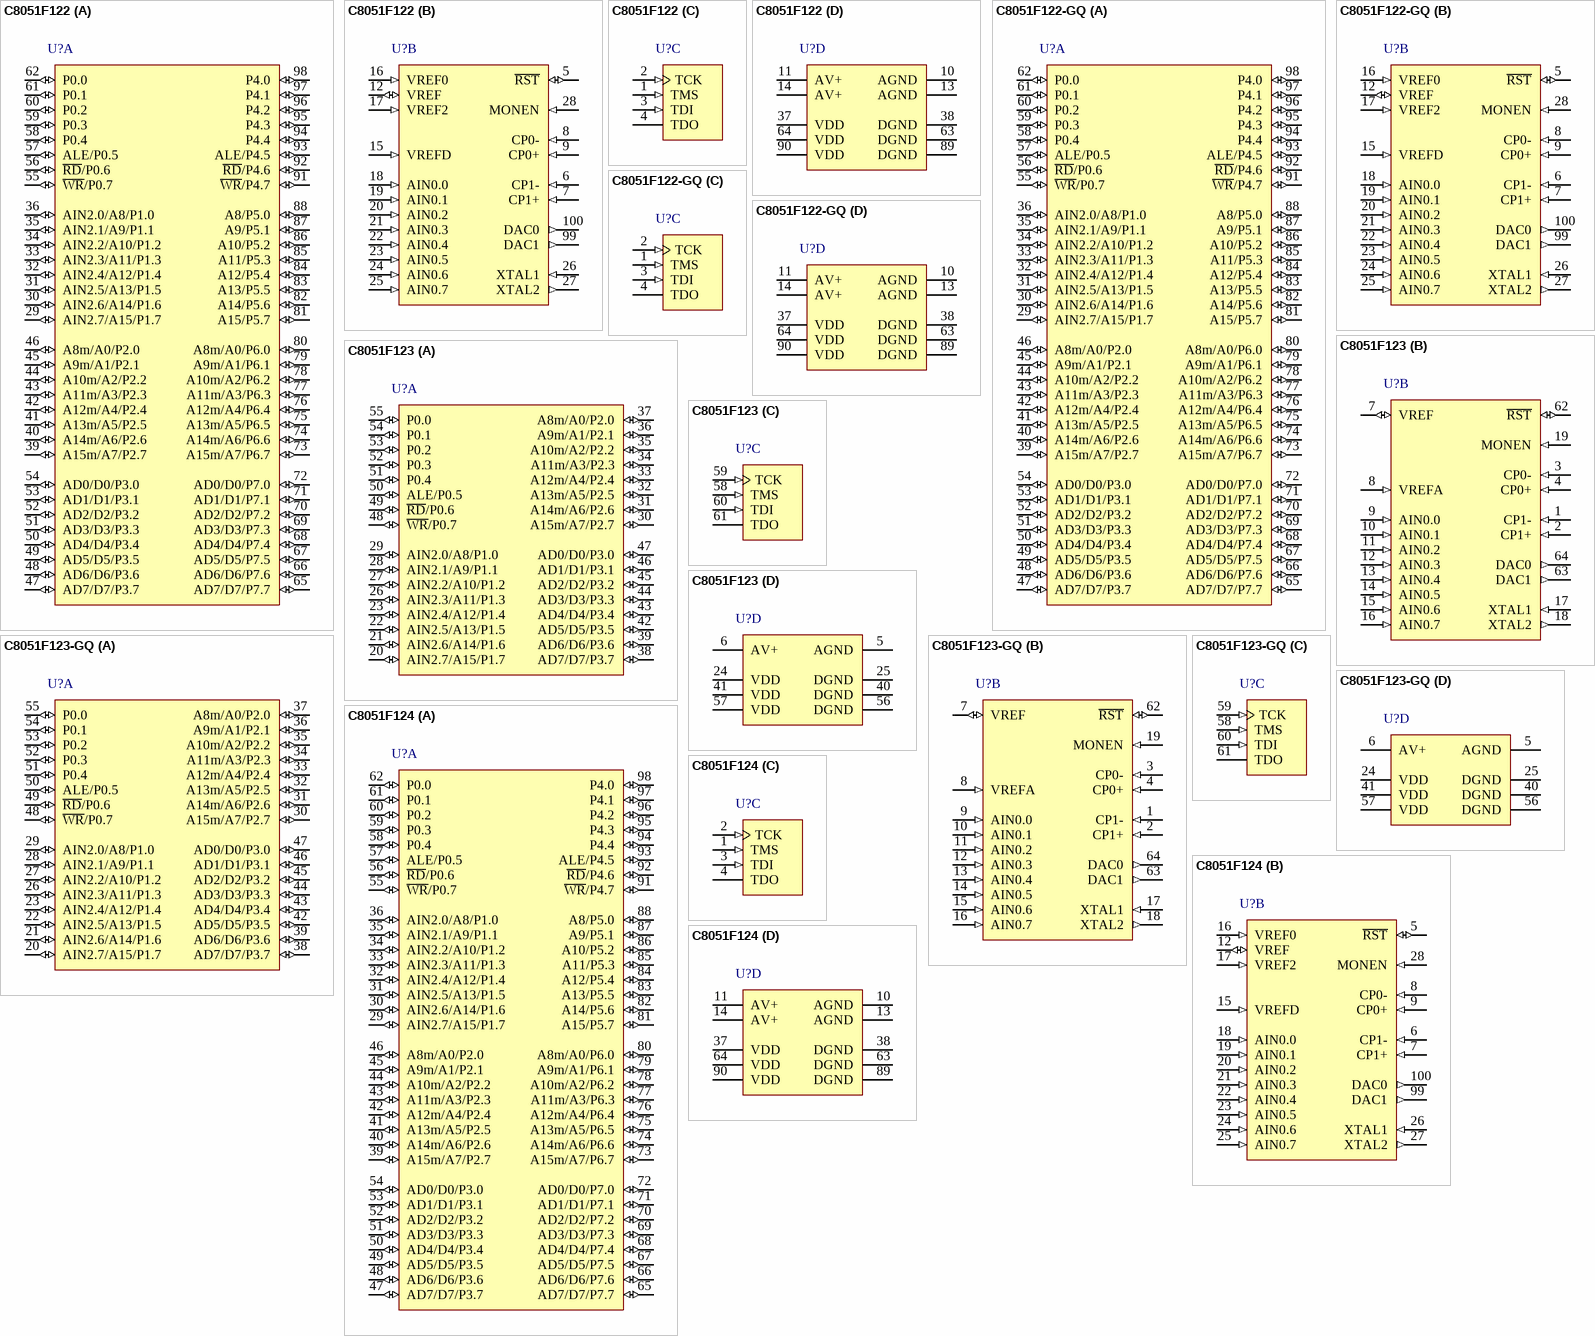
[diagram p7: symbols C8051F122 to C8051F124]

## C8051F122
designator U?
Mixed Signal 128KB ISP Flash MCU, 100 MIPS, 8448B RAM, 64 I/Os, 10-Bit & 8-Bit ADC, 12-Bit DAC, 100-Pin TQFP; Manufacturer: Silicon Labs; PartNumber: C8051F122
footprint TQFP-100_N (Thin QFP, 100-Leads, Body 14x14mm, Pitch 0.5mm, IPC Medium Density)
footprint TQFP-100_L (Thin QFP, 100-Leads, Body 14x14mm, Pitch 0.5mm, IPC High Density)
footprint TQFP-100_M (Thin QFP, 100-Leads, Body 14x14mm, Pitch 0.5mm, IPC Low Density)
part A pins: 29 AIN2.7/A15/P1.7 (io), 30 AIN2.6/A14/P1.6 (io), 31 AIN2.5/A13/P1.5 (io), 32 AIN2.4/A12/P1.4 (io), 33 AIN2.3/A11/P1.3 (io), 34 AIN2.2/A10/P1.2 (io), 35 AIN2.1/A9/P1.1 (io), 36 AIN2.0/A8/P1.0 (io), 39 A15m/A7/P2.7 (io), 40 A14m/A6/P2.6 (io), 41 A13m/A5/P2.5 (io), 42 A12m/A4/P2.4 (io), 43 A11m/A3/P2.3 (io), 44 A10m/A2/P2.2 (io), 45 A9m/A1/P2.1 (io), 46 A8m/A0/P2.0 (io), 47 AD7/D7/P3.7 (io), 48 AD6/D6/P3.6 (io), 49 AD5/D5/P3.5 (io), 50 AD4/D4/P3.4 (io), 51 AD3/D3/P3.3 (io), 52 AD2/D2/P3.2 (io), 53 AD1/D1/P3.1 (io), 54 AD0/D0/P3.0 (io), 55 ~{WR}/P0.7 (io), 56 ~{RD}/P0.6 (io), 57 ALE/P0.5 (io), 58 P0.4 (io), 59 P0.3 (io), 60 P0.2 (io), 61 P0.1 (io), 62 P0.0 (io), 65 AD7/D7/P7.7 (io), 66 AD6/D6/P7.6 (io), 67 AD5/D5/P7.5 (io), 68 AD4/D4/P7.4 (io), 69 AD3/D3/P7.3 (io), 70 AD2/D2/P7.2 (io), 71 AD1/D1/P7.1 (io), 72 AD0/D0/P7.0 (io), 73 A15m/A7/P6.7 (io), 74 A14m/A6/P6.6 (io), 75 A13m/A5/P6.5 (io), 76 A12m/A4/P6.4 (io), 77 A11m/A3/P6.3 (io), 78 A10m/A2/P6.2 (io), 79 A9m/A1/P6.1 (io), 80 A8m/A0/P6.0 (io), 81 A15/P5.7 (io), 82 A14/P5.6 (io), 83 A13/P5.5 (io), 84 A12/P5.4 (io), 85 A11/P5.3 (io), 86 A10/P5.2 (io), 87 A9/P5.1 (io), 88 A8/P5.0 (io), 91 ~{WR}/P4.7 (io), 92 ~{RD}/P4.6 (io), 93 ALE/P4.5 (io), 94 P4.4 (io), 95 P4.3 (io), 96 P4.2 (io), 97 P4.1 (io), 98 P4.0 (io)
part B pins: 5 ~{RST} (io), 6 CP1- (in), 7 CP1+ (in), 8 CP0- (in), 9 CP0+ (in), 12 VREF (io), 15 VREFD (in), 16 VREF0 (in), 17 VREF2 (in), 18 AIN0.0 (in), 19 AIN0.1 (in), 20 AIN0.2 (in), 21 AIN0.3 (in), 22 AIN0.4 (in), 23 AIN0.5 (in), 24 AIN0.6 (in), 25 AIN0.7 (in), 26 XTAL1 (in), 27 XTAL2 (out), 28 MONEN (in), 99 DAC1 (out), 100 DAC0 (out)
part C pins: 1 TMS (in), 2 TCK (in), 3 TDI (in), 4 TDO (hiz)
part D pins: 10 AGND (power), 11 AV+ (power), 13 AGND (power), 14 AV+ (power), 37 VDD (power), 38 DGND (power), 63 DGND (power), 64 VDD (power), 89 DGND (power), 90 VDD (power)

## C8051F122-GQ
designator U?
Mixed Signal 128KB ISP Flash MCU, 100 MIPS, 8448B RAM, 64 I/Os, 10-Bit & 8-Bit ADC, 12-Bit DAC, 100-Pin TQFP, Pb-Free; Manufacturer: Silicon Labs; PartNumber: C8051F122-GQ
footprint TQFP-100_N (Thin QFP, 100-Leads, Body 14x14mm, Pitch 0.5mm, IPC Medium Density)
footprint TQFP-100_L (Thin QFP, 100-Leads, Body 14x14mm, Pitch 0.5mm, IPC High Density)
footprint TQFP-100_M (Thin QFP, 100-Leads, Body 14x14mm, Pitch 0.5mm, IPC Low Density)
part A pins: 29 AIN2.7/A15/P1.7 (io), 30 AIN2.6/A14/P1.6 (io), 31 AIN2.5/A13/P1.5 (io), 32 AIN2.4/A12/P1.4 (io), 33 AIN2.3/A11/P1.3 (io), 34 AIN2.2/A10/P1.2 (io), 35 AIN2.1/A9/P1.1 (io), 36 AIN2.0/A8/P1.0 (io), 39 A15m/A7/P2.7 (io), 40 A14m/A6/P2.6 (io), 41 A13m/A5/P2.5 (io), 42 A12m/A4/P2.4 (io), 43 A11m/A3/P2.3 (io), 44 A10m/A2/P2.2 (io), 45 A9m/A1/P2.1 (io), 46 A8m/A0/P2.0 (io), 47 AD7/D7/P3.7 (io), 48 AD6/D6/P3.6 (io), 49 AD5/D5/P3.5 (io), 50 AD4/D4/P3.4 (io), 51 AD3/D3/P3.3 (io), 52 AD2/D2/P3.2 (io), 53 AD1/D1/P3.1 (io), 54 AD0/D0/P3.0 (io), 55 ~{WR}/P0.7 (io), 56 ~{RD}/P0.6 (io), 57 ALE/P0.5 (io), 58 P0.4 (io), 59 P0.3 (io), 60 P0.2 (io), 61 P0.1 (io), 62 P0.0 (io), 65 AD7/D7/P7.7 (io), 66 AD6/D6/P7.6 (io), 67 AD5/D5/P7.5 (io), 68 AD4/D4/P7.4 (io), 69 AD3/D3/P7.3 (io), 70 AD2/D2/P7.2 (io), 71 AD1/D1/P7.1 (io), 72 AD0/D0/P7.0 (io), 73 A15m/A7/P6.7 (io), 74 A14m/A6/P6.6 (io), 75 A13m/A5/P6.5 (io), 76 A12m/A4/P6.4 (io), 77 A11m/A3/P6.3 (io), 78 A10m/A2/P6.2 (io), 79 A9m/A1/P6.1 (io), 80 A8m/A0/P6.0 (io), 81 A15/P5.7 (io), 82 A14/P5.6 (io), 83 A13/P5.5 (io), 84 A12/P5.4 (io), 85 A11/P5.3 (io), 86 A10/P5.2 (io), 87 A9/P5.1 (io), 88 A8/P5.0 (io), 91 ~{WR}/P4.7 (io), 92 ~{RD}/P4.6 (io), 93 ALE/P4.5 (io), 94 P4.4 (io), 95 P4.3 (io), 96 P4.2 (io), 97 P4.1 (io), 98 P4.0 (io)
part B pins: 5 ~{RST} (io), 6 CP1- (in), 7 CP1+ (in), 8 CP0- (in), 9 CP0+ (in), 12 VREF (io), 15 VREFD (in), 16 VREF0 (in), 17 VREF2 (in), 18 AIN0.0 (in), 19 AIN0.1 (in), 20 AIN0.2 (in), 21 AIN0.3 (in), 22 AIN0.4 (in), 23 AIN0.5 (in), 24 AIN0.6 (in), 25 AIN0.7 (in), 26 XTAL1 (in), 27 XTAL2 (out), 28 MONEN (in), 99 DAC1 (out), 100 DAC0 (out)
part C pins: 1 TMS (in), 2 TCK (in), 3 TDI (in), 4 TDO (hiz)
part D pins: 10 AGND (power), 11 AV+ (power), 13 AGND (power), 14 AV+ (power), 37 VDD (power), 38 DGND (power), 63 DGND (power), 64 VDD (power), 89 DGND (power), 90 VDD (power)

## C8051F123
designator U?
Mixed Signal 128KB ISP Flash MCU, 100 MIPS, 8448B RAM, 32 I/Os, 10-Bit & 8-Bit ADC, 12-Bit DAC, 64-Pin TQFP; Manufacturer: Silicon Labs; PartNumber: C8051F123
footprint TQFP-64_N (Thin QFP, 64-Leads, Body 10x10mm, Pitch 0.5mm, IPC Medium Density)
footprint TQFP-64_L (Thin QFP, 64-Leads, Body 10x10mm, Pitch 0.5mm, IPC High Density)
footprint TQFP-64_M (Thin QFP, 64-Leads, Body 10x10mm, Pitch 0.5mm, IPC Low Density)
part A pins: 20 AIN2.7/A15/P1.7 (io), 21 AIN2.6/A14/P1.6 (io), 22 AIN2.5/A13/P1.5 (io), 23 AIN2.4/A12/P1.4 (io), 26 AIN2.3/A11/P1.3 (io), 27 AIN2.2/A10/P1.2 (io), 28 AIN2.1/A9/P1.1 (io), 29 AIN2.0/A8/P1.0 (io), 30 A15m/A7/P2.7 (io), 31 A14m/A6/P2.6 (io), 32 A13m/A5/P2.5 (io), 33 A12m/A4/P2.4 (io), 34 A11m/A3/P2.3 (io), 35 A10m/A2/P2.2 (io), 36 A9m/A1/P2.1 (io), 37 A8m/A0/P2.0 (io), 38 AD7/D7/P3.7 (io), 39 AD6/D6/P3.6 (io), 42 AD5/D5/P3.5 (io), 43 AD4/D4/P3.4 (io), 44 AD3/D3/P3.3 (io), 45 AD2/D2/P3.2 (io), 46 AD1/D1/P3.1 (io), 47 AD0/D0/P3.0 (io), 48 ~{WR}/P0.7 (io), 49 ~{RD}/P0.6 (io), 50 ALE/P0.5 (io), 51 P0.4 (io), 52 P0.3 (io), 53 P0.2 (io), 54 P0.1 (io), 55 P0.0 (io)
part B pins: 1 CP1- (in), 2 CP1+ (in), 3 CP0- (in), 4 CP0+ (in), 7 VREF (io), 8 VREFA (in), 9 AIN0.0 (in), 10 AIN0.1 (in), 11 AIN0.2 (in), 12 AIN0.3 (in), 13 AIN0.4 (in), 14 AIN0.5 (in), 15 AIN0.6 (in), 16 AIN0.7 (in), 17 XTAL1 (in), 18 XTAL2 (out), 19 MONEN (in), 62 ~{RST} (io), 63 DAC1 (out), 64 DAC0 (out)
part C pins: 58 TMS (in), 59 TCK (in), 60 TDI (in), 61 TDO (hiz)
part D pins: 5 AGND (power), 6 AV+ (power), 24 VDD (power), 25 DGND (power), 40 DGND (power), 41 VDD (power), 56 DGND (power), 57 VDD (power)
